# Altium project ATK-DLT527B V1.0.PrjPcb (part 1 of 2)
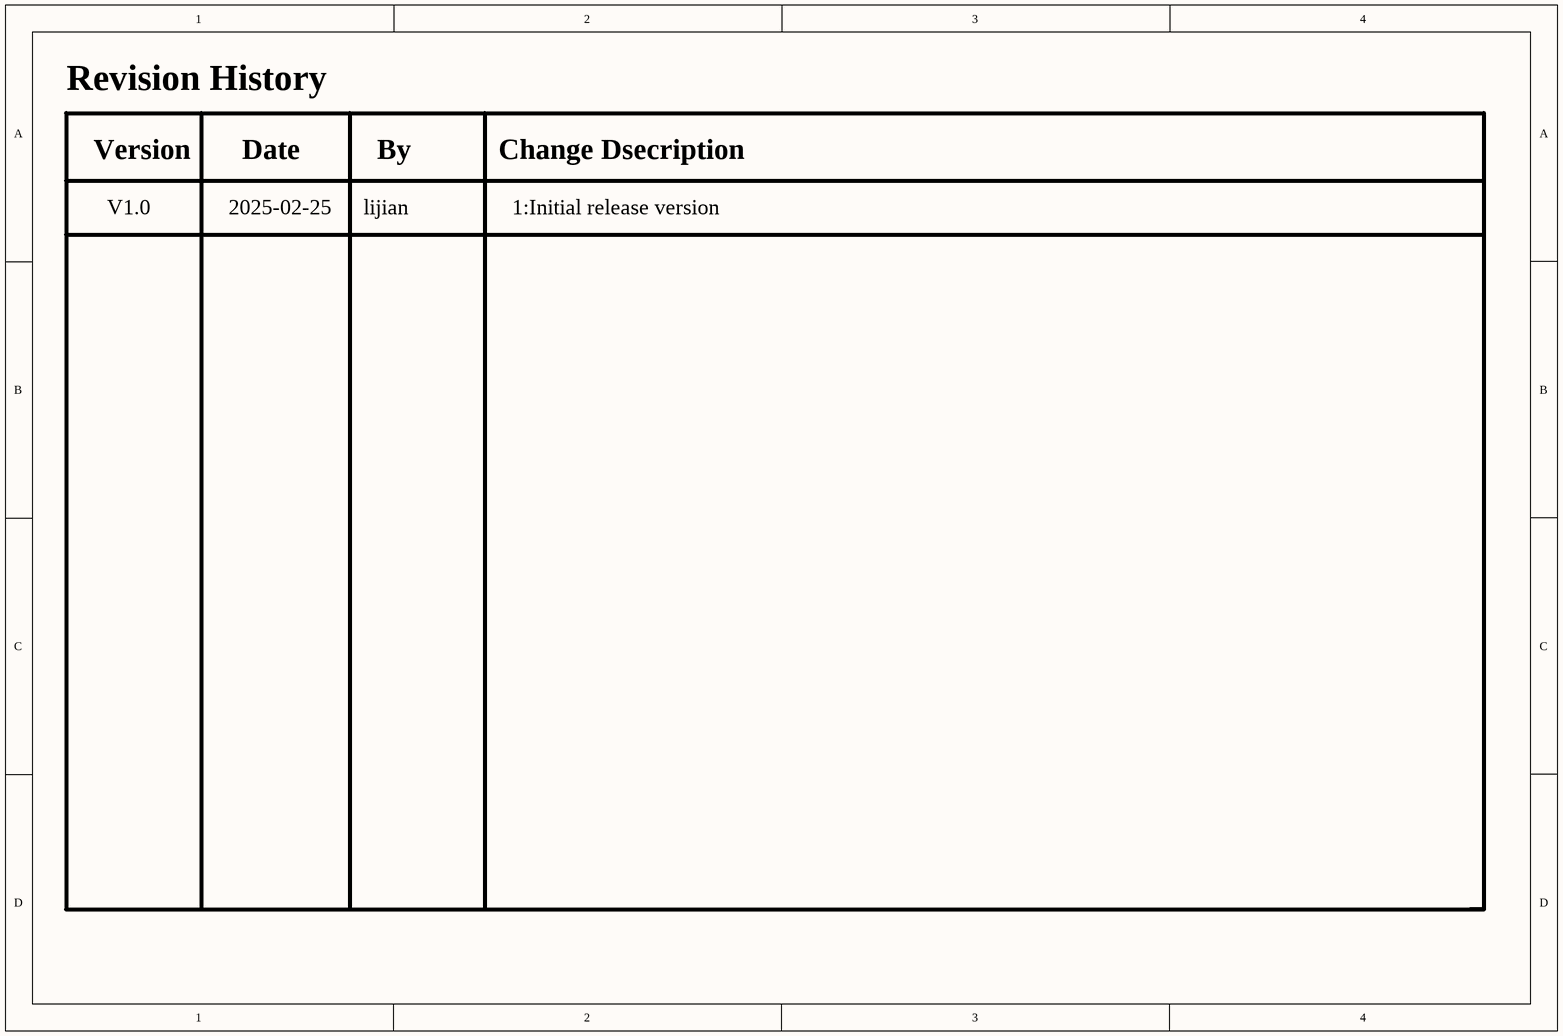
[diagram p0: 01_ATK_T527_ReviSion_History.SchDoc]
13 sheets, 679 parts. Net scope: global (net labels, ports and power ports of the same name join across sheets).
Sheets:
  01_ATK_T527_ReviSion_History.SchDoc
  02_ATK_T527_CORE.SchDoc
  03_ATK_T527_POWER.SchDoc
  04_ATK_T527_NET1.SchDoc
  05_ATK_T527_NET2.SchDoc
  06_ATK_T527_DISPLAY.SchDoc
  07_ATK_T527_HDMI&DP.SchDoc
  08_ATK_T527_USBOTG&HOST.SchDoc
  09_ATK_T527_AUDIO.SchDoc
  10_ATK_T527_MIPICSI.SchDoc
  11_ATK_T527_CAN485.SchDoc
  12_ATK_T527_DEVICE1.SchDoc
  13_ATK_T527_DEVICE2.SchDoc

## Sheet 01_ATK_T527_ReviSion_History.SchDoc
size A4; Organization: Altium Limited; Address1: L3, 12a Rodborough Rd; Address2: Frenchs Forest; Address3: NSW; Address4: Australia 2086

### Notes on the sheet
- Revision History
- Version
- Date
- By
- Change Dsecription
- V1.0
- 2025-02-25
- lijian
- 1:Initial release version

## Sheet 02_ATK_T527_CORE.SchDoc
size A3; Date: 13; Author: ALIENTEK; Revision: 0; Version: V1.0; SheetSize: A3
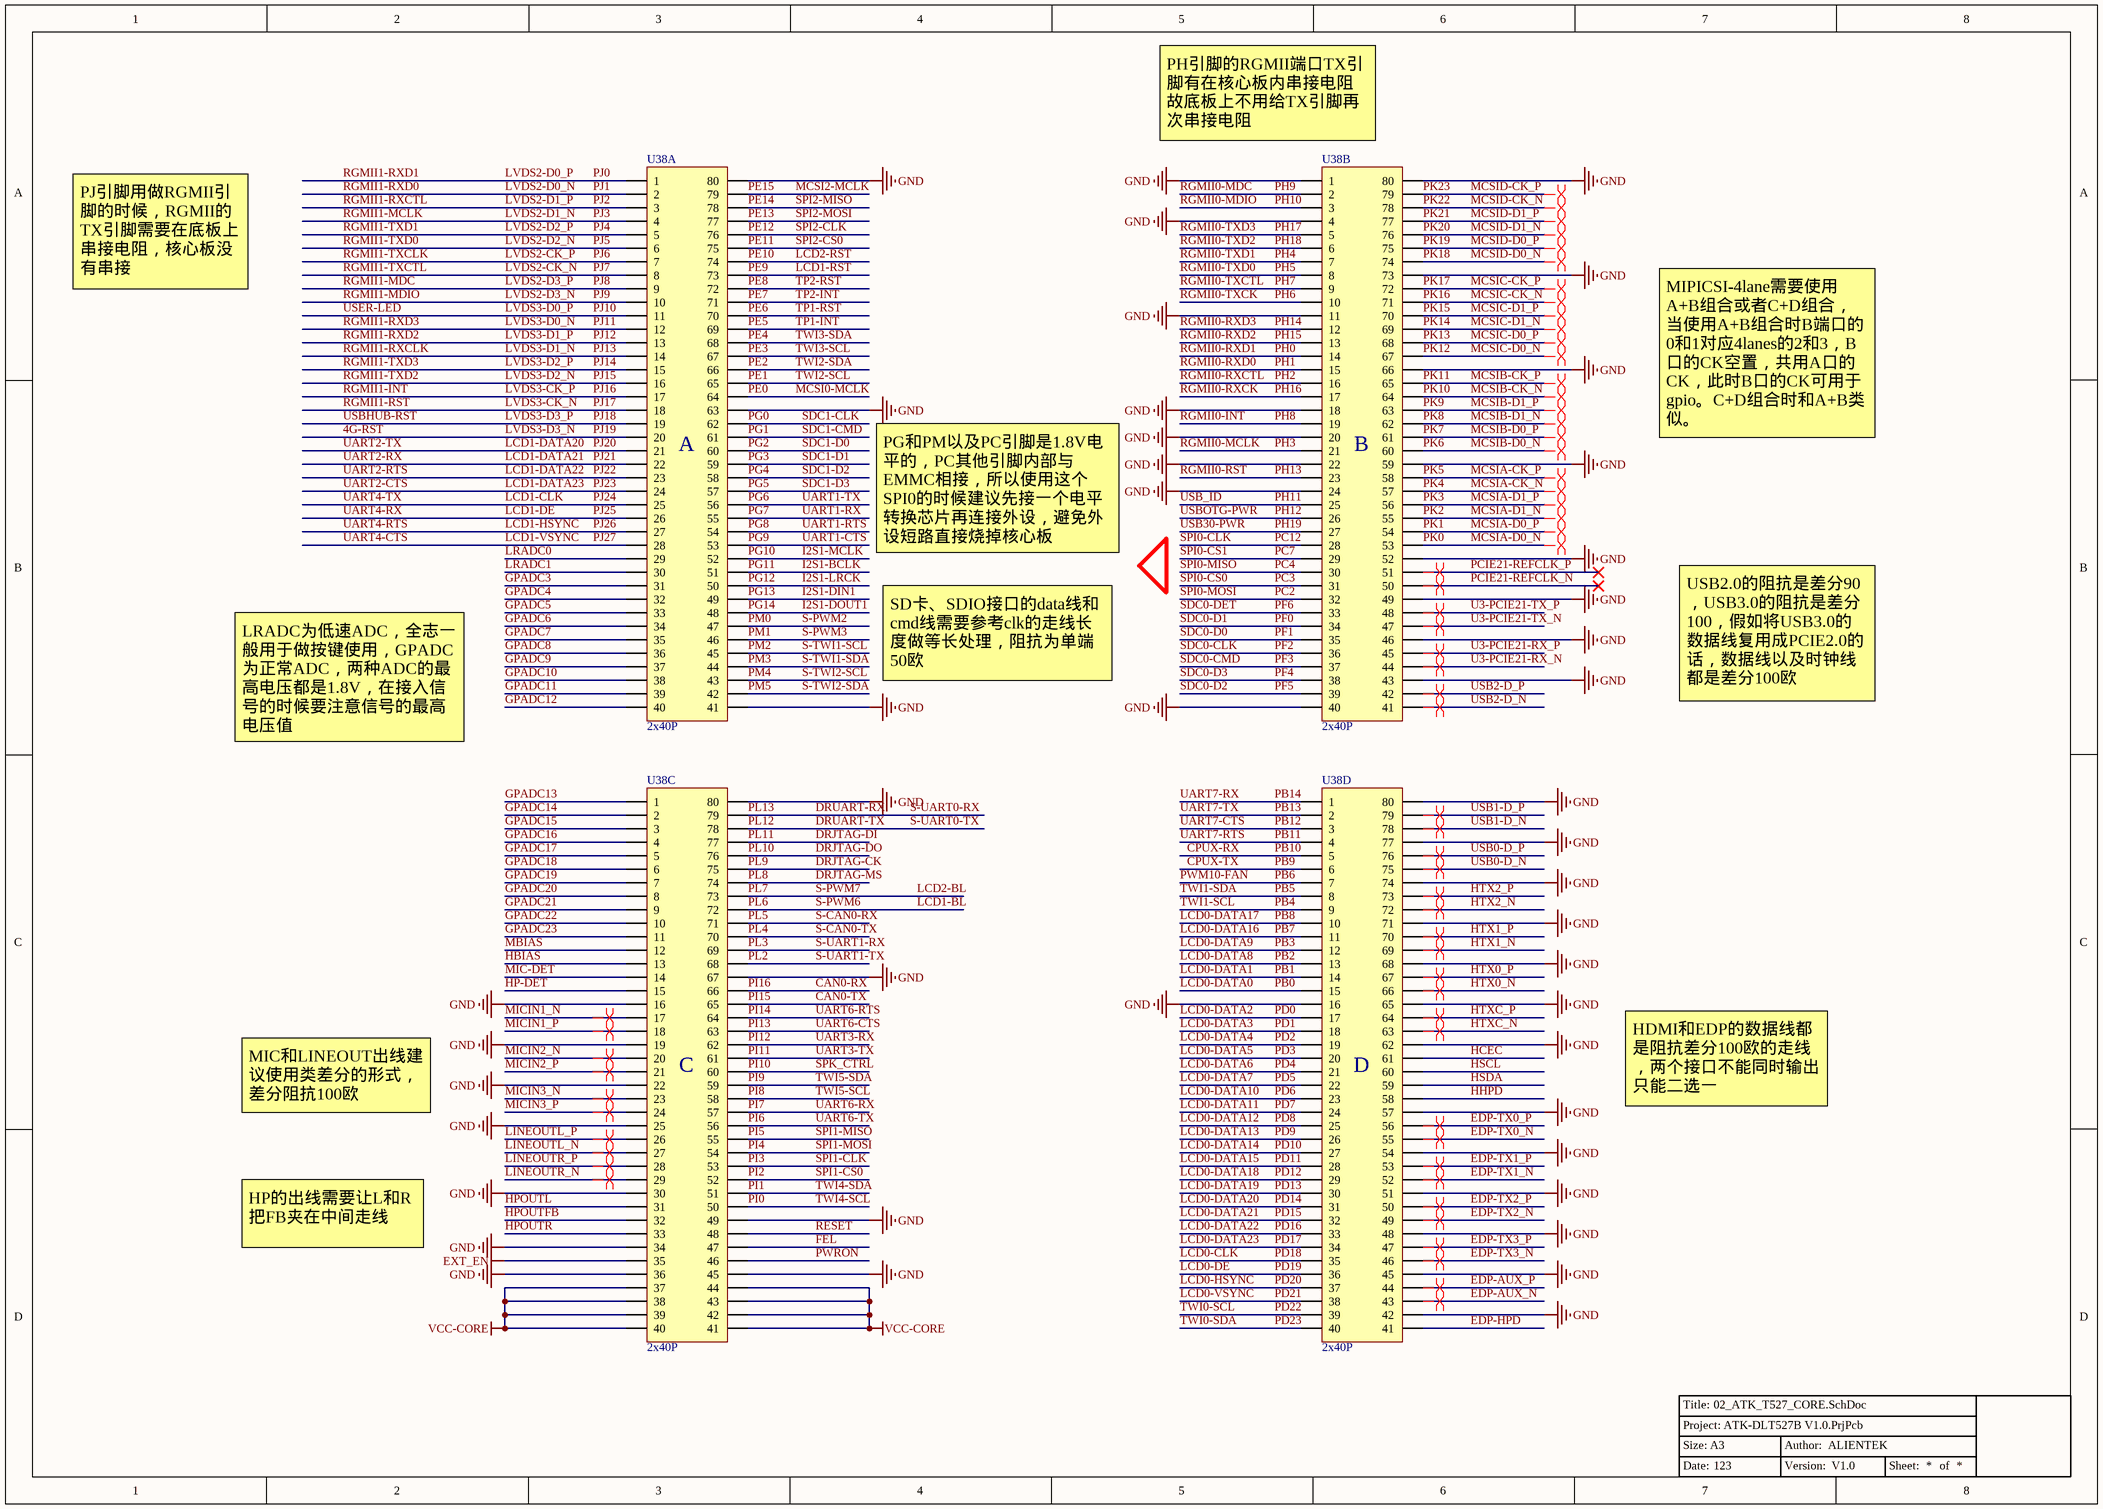
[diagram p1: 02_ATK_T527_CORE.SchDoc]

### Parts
U38  2x40P  [ATK-CLT527B-CORE]  (parts A,B,C,D of 4)

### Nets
EXT_EN: U38.C35(35)
GND: U38.A41(41) U38.A63(63) U38.A80(80) U38.B1(1) U38.B4(4) U38.B11(11) U38.B18(18) U38.B20(20) U38.B22(22) U38.B24(24) U38.B40(40) U38.B43(43) U38.B46(46) U38.B49(49) U38.B52(52) U38.B59(59) U38.B66(66) U38.B73(73) U38.B80(80) U38.C16(16) U38.C19(19) U38.C22(22) U38.C25(25) U38.C30(30) U38.C34(34) U38.C36(36) U38.C45(45) U38.C49(49) U38.C67(67) U38.C80(80) U38.D16(16) U38.D42(42) U38.D45(45) U38.D48(48) U38.D51(51) U38.D54(54) U38.D57(57) U38.D62(62) U38.D65(65) U38.D68(68) U38.D71(71) U38.D74(74) U38.D77(77) U38.D80(80)
VCC-CORE: U38.C37(37) U38.C38(38) U38.C39(39) U38.C40(40) U38.C41(41) U38.C42(42) U38.C43(43) U38.C44(44)
4G-RST: U38.A20(20)  [also labelled LVDS3-D3_N, PJ19]
CAN0-RX: U38.C66(66)  [also labelled PI16]
CAN0-TX: U38.C65(65)  [also labelled PI15]
CPUX-RX: U38.D5(5)  [also labelled PB10]
CPUX-TX: U38.D6(6)  [also labelled PB9]
DRJTAG-CK: U38.C75(75)  [also labelled PL9]
DRJTAG-DI: U38.C77(77)  [also labelled PL11]
DRJTAG-DO: U38.C76(76)  [also labelled PL10]
DRJTAG-MS: U38.C74(74)  [also labelled PL8]
DRUART-RX: U38.C79(79)  [also labelled PL13, S-UART0-RX]
DRUART-TX: U38.C78(78)  [also labelled PL12, S-UART0-TX]
EDP-AUX_N: U38.D43(43)
EDP-AUX_P: U38.D44(44)
EDP-HPD: U38.D41(41)
EDP-TX0_N: U38.D55(55)
EDP-TX0_P: U38.D56(56)
EDP-TX1_N: U38.D52(52)
EDP-TX1_P: U38.D53(53)
EDP-TX2_N: U38.D49(49)
EDP-TX2_P: U38.D50(50)
EDP-TX3_N: U38.D46(46)
EDP-TX3_P: U38.D47(47)
FEL: U38.C47(47)
GPADC3: U38.A31(31)
GPADC4: U38.A32(32)
GPADC5: U38.A33(33)
GPADC6: U38.A34(34)
GPADC7: U38.A35(35)
GPADC8: U38.A36(36)
GPADC9: U38.A37(37)
GPADC10: U38.A38(38)
GPADC11: U38.A39(39)
GPADC12: U38.A40(40)
GPADC13: U38.C1(1)
GPADC14: U38.C2(2)
GPADC15: U38.C3(3)
GPADC16: U38.C4(4)
GPADC17: U38.C5(5)
GPADC18: U38.C6(6)
GPADC19: U38.C7(7)
GPADC20: U38.C8(8)
GPADC21: U38.C9(9)
GPADC22: U38.C10(10)
GPADC23: U38.C11(11)
HBIAS: U38.C13(13)
HCEC: U38.D61(61)
HHPD: U38.D58(58)
HP-DET: U38.C15(15)
HPOUTFB: U38.C32(32)
HPOUTL: U38.C31(31)
HPOUTR: U38.C33(33)
HSCL: U38.D60(60)
HSDA: U38.D59(59)
HTX0_N: U38.D66(66)
HTX0_P: U38.D67(67)
HTX1_N: U38.D69(69)
HTX1_P: U38.D70(70)
HTX2_N: U38.D72(72)
HTX2_P: U38.D73(73)
HTXC_N: U38.D63(63)
HTXC_P: U38.D64(64)
I2S1-BCLK: U38.A51(51)  [also labelled PG11]
I2S1-DIN1: U38.A49(49)  [also labelled PG13]
I2S1-DOUT1: U38.A48(48)  [also labelled PG14]
I2S1-LRCK: U38.A50(50)  [also labelled PG12]
I2S1-MCLK: U38.A52(52)  [also labelled PG10]
LCD0-CLK: U38.D35(35)  [also labelled PD18]
LCD0-DATA0: U38.D15(15)  [also labelled PB0]
LCD0-DATA1: U38.D14(14)  [also labelled PB1]
LCD0-DATA2: U38.D17(17)  [also labelled PD0]
LCD0-DATA3: U38.D18(18)  [also labelled PD1]
LCD0-DATA4: U38.D19(19)  [also labelled PD2]
LCD0-DATA5: U38.D20(20)  [also labelled PD3]
LCD0-DATA6: U38.D21(21)  [also labelled PD4]
LCD0-DATA7: U38.D22(22)  [also labelled PD5]
LCD0-DATA8: U38.D13(13)  [also labelled PB2]
LCD0-DATA9: U38.D12(12)  [also labelled PB3]
LCD0-DATA10: U38.D23(23)  [also labelled PD6]
LCD0-DATA11: U38.D24(24)  [also labelled PD7]
LCD0-DATA12: U38.D25(25)  [also labelled PD8]
LCD0-DATA13: U38.D26(26)  [also labelled PD9]
LCD0-DATA14: U38.D27(27)  [also labelled PD10]
LCD0-DATA15: U38.D28(28)  [also labelled PD11]
LCD0-DATA16: U38.D11(11)  [also labelled PB7]
LCD0-DATA17: U38.D10(10)  [also labelled PB8]
LCD0-DATA18: U38.D29(29)  [also labelled PD12]
LCD0-DATA19: U38.D30(30)  [also labelled PD13]
LCD0-DATA20: U38.D31(31)  [also labelled PD14]
LCD0-DATA21: U38.D32(32)  [also labelled PD15]
LCD0-DATA22: U38.D33(33)  [also labelled PD16]
LCD0-DATA23: U38.D34(34)  [also labelled PD17]
LCD0-DE: U38.D36(36)  [also labelled PD19]
LCD0-HSYNC: U38.D37(37)  [also labelled PD20]
LCD0-VSYNC: U38.D38(38)  [also labelled PD21]
LCD1-BL: U38.C72(72)  [also labelled PL6, S-PWM6]
LCD1-CLK: U38.A25(25)  [also labelled PJ24, UART4-TX]
LCD1-DATA20: U38.A21(21)  [also labelled PJ20, UART2-TX]
LCD1-DATA21: U38.A22(22)  [also labelled PJ21, UART2-RX]
LCD1-DATA22: U38.A23(23)  [also labelled PJ22, UART2-RTS]
LCD1-DATA23: U38.A24(24)  [also labelled PJ23, UART2-CTS]
LCD1-DE: U38.A26(26)  [also labelled PJ25, UART4-RX]
LCD1-HSYNC: U38.A27(27)  [also labelled PJ26, UART4-RTS]
LCD1-RST: U38.A73(73)  [also labelled PE9]
LCD1-VSYNC: U38.A28(28)  [also labelled PJ27, UART4-CTS]
LCD2-BL: U38.C73(73)  [also labelled PL7, S-PWM7]
LCD2-RST: U38.A74(74)  [also labelled PE10]
LINEOUTL_N: U38.C27(27)
LINEOUTL_P: U38.C26(26)
LINEOUTR_N: U38.C29(29)
LINEOUTR_P: U38.C28(28)
LRADC0: U38.A29(29)
LRADC1: U38.A30(30)
LVDS2-CK_N: U38.A8(8)  [also labelled PJ7, RGMII1-TXCTL]
LVDS2-CK_P: U38.A7(7)  [also labelled PJ6, RGMII1-TXCLK]
LVDS2-D0_N: U38.A2(2)  [also labelled PJ1, RGMII1-RXD0]
LVDS2-D0_P: U38.A1(1)  [also labelled PJ0, RGMII1-RXD1]
LVDS2-D1_N: U38.A4(4)  [also labelled PJ3, RGMII1-MCLK]
LVDS2-D1_P: U38.A3(3)  [also labelled PJ2, RGMII1-RXCTL]
LVDS2-D2_N: U38.A6(6)  [also labelled PJ5, RGMII1-TXD0]
LVDS2-D2_P: U38.A5(5)  [also labelled PJ4, RGMII1-TXD1]
LVDS2-D3_N: U38.A10(10)  [also labelled PJ9, RGMII1-MDIO]
LVDS2-D3_P: U38.A9(9)  [also labelled PJ8, RGMII1-MDC]
LVDS3-CK_N: U38.A18(18)  [also labelled PJ17, RGMII1-RST]
LVDS3-CK_P: U38.A17(17)  [also labelled PJ16, RGMII1-INT]
LVDS3-D0_N: U38.A12(12)  [also labelled PJ11, RGMII1-RXD3]
LVDS3-D0_P: U38.A11(11)  [also labelled PJ10, USER-LED]
LVDS3-D1_N: U38.A14(14)  [also labelled PJ13, RGMII1-RXCLK]
LVDS3-D1_P: U38.A13(13)  [also labelled PJ12, RGMII1-RXD2]
LVDS3-D2_N: U38.A16(16)  [also labelled PJ15, RGMII1-TXD2]
LVDS3-D2_P: U38.A15(15)  [also labelled PJ14, RGMII1-TXD3]
LVDS3-D3_P: U38.A19(19)  [also labelled PJ18, USBHUB-RST]
MBIAS: U38.C12(12)
MCSI0-MCLK: U38.A64(64)  [also labelled PE0]
MCSI2-MCLK: U38.A79(79)  [also labelled PE15]
MCSIA-CK_N: U38.B57(57)  [also labelled PK4]
MCSIA-CK_P: U38.B58(58)  [also labelled PK5]
MCSIA-D0_N: U38.B53(53)  [also labelled PK0]
MCSIA-D0_P: U38.B54(54)  [also labelled PK1]
MCSIA-D1_N: U38.B55(55)  [also labelled PK2]
MCSIA-D1_P: U38.B56(56)  [also labelled PK3]
MCSIB-CK_N: U38.B64(64)  [also labelled PK10]
MCSIB-CK_P: U38.B65(65)  [also labelled PK11]
MCSIB-D0_N: U38.B60(60)  [also labelled PK6]
MCSIB-D0_P: U38.B61(61)  [also labelled PK7]
MCSIB-D1_N: U38.B62(62)  [also labelled PK8]
MCSIB-D1_P: U38.B63(63)  [also labelled PK9]
MCSIC-CK_N: U38.B71(71)  [also labelled PK16]
MCSIC-CK_P: U38.B72(72)  [also labelled PK17]
MCSIC-D0_N: U38.B67(67)  [also labelled PK12]
MCSIC-D0_P: U38.B68(68)  [also labelled PK13]
MCSIC-D1_N: U38.B69(69)  [also labelled PK14]
MCSIC-D1_P: U38.B70(70)  [also labelled PK15]
MCSID-CK_N: U38.B78(78)  [also labelled PK22]
MCSID-CK_P: U38.B79(79)  [also labelled PK23]
MCSID-D0_N: U38.B74(74)  [also labelled PK18]
MCSID-D0_P: U38.B75(75)  [also labelled PK19]
MCSID-D1_N: U38.B76(76)  [also labelled PK20]
MCSID-D1_P: U38.B77(77)  [also labelled PK21]
MIC-DET: U38.C14(14)
MICIN1_N: U38.C17(17)
MICIN1_P: U38.C18(18)
MICIN2_N: U38.C20(20)
MICIN2_P: U38.C21(21)
MICIN3_N: U38.C23(23)
MICIN3_P: U38.C24(24)
PB4: U38.D9(9)  [also labelled TWI1-SCL]  [project net CT2_SCL]
PB5: U38.D8(8)  [also labelled TWI1-SDA]  [project net CT2_SDA]
PB6: U38.D7(7)  [also labelled PWM10-FAN]
PB11: U38.D4(4)  [also labelled UART7-RTS]
PB12: U38.D3(3)  [also labelled UART7-CTS]
PB13: U38.D2(2)  [also labelled UART7-TX]
PB14: U38.D1(1)  [also labelled UART7-RX]
PC2: U38.B32(32)  [also labelled SPI0-MOSI]
PC3: U38.B31(31)  [also labelled SPI0-CS0]
PC4: U38.B30(30)  [also labelled SPI0-MISO]
PC7: U38.B29(29)  [also labelled SPI0-CS1]
PC12: U38.B28(28)  [also labelled SPI0-CLK]
PCIE21-REFCLK_N: U38.B50(50)
PCIE21-REFCLK_P: U38.B51(51)
PD22: U38.D39(39)  [also labelled TWI0-SCL]  [project net CT1_SCL]
PD23: U38.D40(40)  [also labelled TWI0-SDA]  [project net CT1_SDA]
PE1: U38.A65(65)  [also labelled TWI2-SCL]
PE2: U38.A66(66)  [also labelled TWI2-SDA]
PE3: U38.A67(67)  [also labelled TWI3-SCL]
PE4: U38.A68(68)  [also labelled TWI3-SDA]
PE5: U38.A69(69)  [also labelled TP1-INT]  [project net CT1_INT]
PE6: U38.A70(70)  [also labelled TP1-RST]  [project net CT1_RST]
PE7: U38.A71(71)  [also labelled TP2-INT]  [project net CT2_INT]
PE8: U38.A72(72)  [also labelled TP2-RST]  [project net CT2_RST]
PE11: U38.A75(75)  [also labelled SPI2-CS0]
PE12: U38.A76(76)  [also labelled SPI2-CLK]
PE13: U38.A77(77)  [also labelled SPI2-MOSI]
PE14: U38.A78(78)  [also labelled SPI2-MISO]
PF0: U38.B34(34)  [also labelled SDC0-D1]
PF1: U38.B35(35)  [also labelled SDC0-D0]
PF2: U38.B36(36)  [also labelled SDC0-CLK]
PF3: U38.B37(37)  [also labelled SDC0-CMD]
PF4: U38.B38(38)  [also labelled SDC0-D3]
PF5: U38.B39(39)  [also labelled SDC0-D2]
PF6: U38.B33(33)  [also labelled SDC0-DET]
PG0: U38.A62(62)  [also labelled SDC1-CLK]
PG1: U38.A61(61)  [also labelled SDC1-CMD]
PG2: U38.A60(60)  [also labelled SDC1-D0]
PG3: U38.A59(59)  [also labelled SDC1-D1]
PG4: U38.A58(58)  [also labelled SDC1-D2]
PG5: U38.A57(57)  [also labelled SDC1-D3]
PG6: U38.A56(56)  [also labelled UART1-TX]
PG7: U38.A55(55)  [also labelled UART1-RX]
PG8: U38.A54(54)  [also labelled UART1-RTS]
PG9: U38.A53(53)  [also labelled UART1-CTS]
PH0: U38.B14(14)  [also labelled RGMII0-RXD1]
PH1: U38.B15(15)  [also labelled RGMII0-RXD0]
PH2: U38.B16(16)  [also labelled RGMII0-RXCTL]
PH3: U38.B21(21)  [also labelled RGMII0-MCLK]
PH4: U38.B7(7)  [also labelled RGMII0-TXD1]
PH5: U38.B8(8)  [also labelled RGMII0-TXD0]
PH6: U38.B10(10)  [also labelled RGMII0-TXCK]
PH7: U38.B9(9)  [also labelled RGMII0-TXCTL]
PH8: U38.B19(19)  [also labelled RGMII0-INT]
PH9: U38.B2(2)  [also labelled RGMII0-MDC]
PH10: U38.B3(3)  [also labelled RGMII0-MDIO]
PH11: U38.B25(25)  [also labelled USB_ID]
PH12: U38.B26(26)  [also labelled USBOTG-PWR]
PH13: U38.B23(23)  [also labelled RGMII0-RST]
PH14: U38.B12(12)  [also labelled RGMII0-RXD3]
PH15: U38.B13(13)  [also labelled RGMII0-RXD2]
PH16: U38.B17(17)  [also labelled RGMII0-RXCK]
PH17: U38.B5(5)  [also labelled RGMII0-TXD3]
PH18: U38.B6(6)  [also labelled RGMII0-TXD2]
PH19: U38.B27(27)  [also labelled USB30-PWR]
PI0: U38.C50(50)  [also labelled TWI4-SCL]
PI1: U38.C51(51)  [also labelled TWI4-SDA]
PI2: U38.C52(52)  [also labelled SPI1-CS0]
PI3: U38.C53(53)  [also labelled SPI1-CLK]
PI4: U38.C54(54)  [also labelled SPI1-MOSI]
PI5: U38.C55(55)  [also labelled SPI1-MISO]
PI6: U38.C56(56)  [also labelled UART6-TX]
PI7: U38.C57(57)  [also labelled UART6-RX]
PI8: U38.C58(58)  [also labelled TWI5-SCL]
PI9: U38.C59(59)  [also labelled TWI5-SDA]
PI10: U38.C60(60)  [also labelled SPK_CTRL]
PI11: U38.C61(61)  [also labelled UART3-TX]
PI12: U38.C62(62)  [also labelled UART3-RX]
PI13: U38.C63(63)  [also labelled UART6-CTS]
PI14: U38.C64(64)  [also labelled UART6-RTS]
PL2: U38.C68(68)  [also labelled S-UART1-TX]
PL3: U38.C69(69)  [also labelled S-UART1-RX]
PL4: U38.C70(70)  [also labelled S-CAN0-TX]
PL5: U38.C71(71)  [also labelled S-CAN0-RX]
PM0: U38.A47(47)  [also labelled S-PWM2]
PM1: U38.A46(46)  [also labelled S-PWM3]
PM2: U38.A45(45)  [also labelled S-TWI1-SCL]
PM3: U38.A44(44)  [also labelled S-TWI1-SDA]
PM4: U38.A43(43)  [also labelled S-TWI2-SCL]
PM5: U38.A42(42)  [also labelled S-TWI2-SDA]
PWRON: U38.C46(46)
RESET: U38.C48(48)
U3-PCIE21-RX_N: U38.B44(44)
U3-PCIE21-RX_P: U38.B45(45)
U3-PCIE21-TX_N: U38.B47(47)
U3-PCIE21-TX_P: U38.B48(48)
USB0-D_N: U38.D75(75)
USB0-D_P: U38.D76(76)
USB1-D_N: U38.D78(78)
USB1-D_P: U38.D79(79)
USB2-D_N: U38.B41(41)
USB2-D_P: U38.B42(42)

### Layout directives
differential pair: EDP-AUX_N, EDP-AUX_P, EDP-TX0_N, EDP-TX0_P, EDP-TX1_N, EDP-TX1_P, EDP-TX2_N, EDP-TX2_P, EDP-TX3_N, EDP-TX3_P, HTX0_N, HTX0_P, HTX1_N, HTX1_P, HTX2_N, HTX2_P, HTXC_N, HTXC_P, LINEOUTL_N, LINEOUTL_P, LINEOUTR_N, LINEOUTR_P, MCSIA-CK_N, MCSIA-CK_P, MCSIA-D0_N, MCSIA-D0_P, MCSIA-D1_N, MCSIA-D1_P, MCSIB-CK_N, MCSIB-CK_P, MCSIB-D0_N, MCSIB-D0_P, MCSIB-D1_N, MCSIB-D1_P, MCSIC-CK_N, MCSIC-CK_P, MCSIC-D0_N, MCSIC-D0_P, MCSIC-D1_N, MCSIC-D1_P, MCSID-CK_N, MCSID-CK_P, MCSID-D0_N, MCSID-D0_P, MCSID-D1_N, MCSID-D1_P, MICIN1_N, MICIN1_P, MICIN2_N, MICIN2_P, MICIN3_N, MICIN3_P, PCIE21-REFCLK_N, PCIE21-REFCLK_P, U3-PCIE21-RX_N, U3-PCIE21-RX_P, U3-PCIE21-TX_N, U3-PCIE21-TX_P, USB0-D_N, USB0-D_P, USB1-D_N, USB1-D_P, USB2-D_N, USB2-D_P

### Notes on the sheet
- (near U38) PH引脚的RGMII端口TX引脚有在核心板内串接电阻故底板上不用给TX引脚再次串接电阻
- PJ引脚用做RGMII引脚的时候，RGMII的TX引脚需要在底板上串接电阻，核心板没有串接
- MIPICSI-4lane需要使用A+B组合或者C+D组合，当使用A+B组合时B端口的0和1对应4lanes的2和3，B口的CK空置，共用A口的CK，此时B口的CK可用于gpio。C+D组合时和A+B类似。
- PG和PM以及PC引脚是1.8V电平的，PC其他引脚内部与EMMC相接，所以使用这个SPI0的时候建议先接一个电平转换芯片再连接外设，避免外设短路直接烧掉核心板
- SD卡、SDIO接口的data线和cmd线需要参考clk的走线长度做等长处理，阻抗为单端50欧
- USB2.0的阻抗是差分90，USB3.0的阻抗是差分100，假如将USB3.0的数据线复用成PCIE2.0的话，数据线以及时钟线都是差分100欧
- LRADC为低速ADC，全志一般用于做按键使用，GPADC为正常ADC，两种ADC的最高电压都是1.8V，在接入信号的时候要注意信号的最高电压值
- MIC和LINEOUT出线建议使用类差分的形式，差分阻抗100欧
- HDMI和EDP的数据线都是阻抗差分100欧的走线，两个接口不能同时输出只能二选一
- HP的出线需要让L和R把FB夹在中间走线

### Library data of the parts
U38 = CLMP257B-CORE

## Sheet 03_ATK_T527_POWER.SchDoc
size A4; Author: ALIENTEK; Revision: 0; Version: V1.0; SheetSize: A4
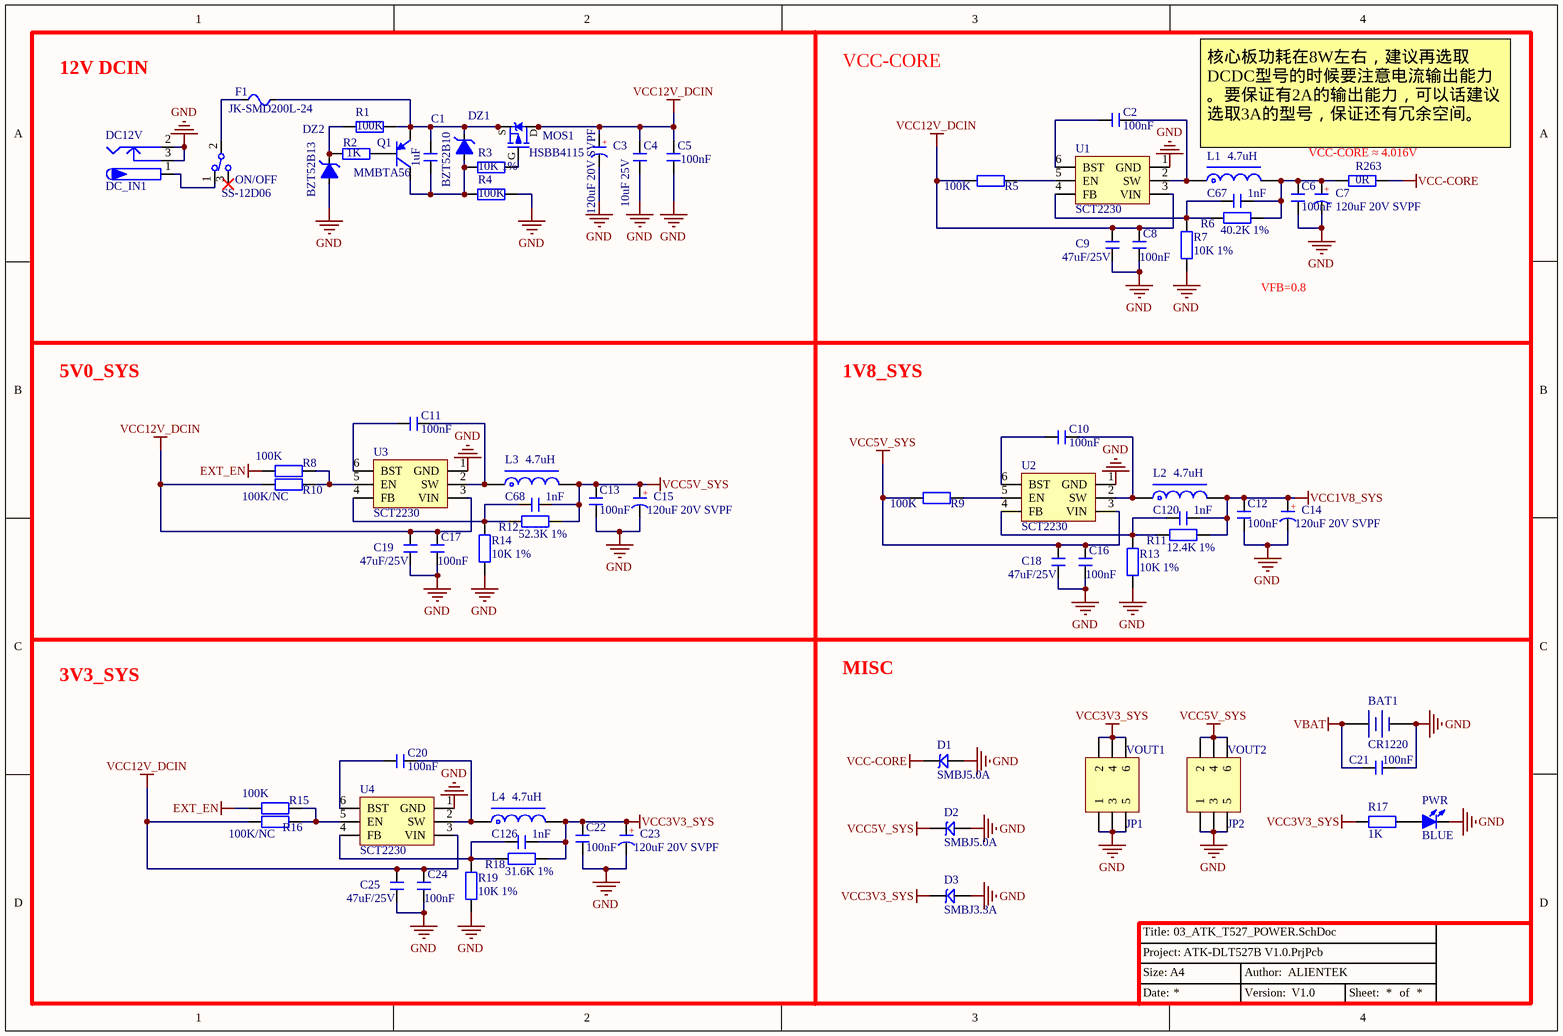
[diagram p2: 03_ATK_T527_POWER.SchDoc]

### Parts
(Parts that share a designator on the sheet are numbered #1, #2 ... from top to bottom, then left to right.)
BAT1  CR1220  [CR1220_A]
C1  1uF  [C 0402]
C2  100nF  [C 0402]
C3  120uF 20V SVPF  [CM D(6.3*7.7)]
C4  10uF 25V  [C 1206]
C5  100nF  [C 0402]
C6  100nF  [C 0402]
C7  120uF 20V SVPF  [CM D(6.3*7.7)]
C8  100nF  [C 0402]
C9  47uF/25V  [C 1206]
C10  100nF  [C 0402]
C11  100nF  [C 0402]
C12  100nF  [C 0402]
C13  100nF  [C 0402]
C14  120uF 20V SVPF  [CM D(6.3*7.7)]
C15  120uF 20V SVPF  [CM D(6.3*7.7)]
C16  100nF  [C 0402]
C17  100nF  [C 0402]
C18  47uF/25V  [C 1206]
C19  47uF/25V  [C 1206]
C20  100nF  [C 0402]
C21  100nF  [C 0402]
C22  100nF  [C 0402]
C23  120uF 20V SVPF  [CM D(6.3*7.7)]
C24  100nF  [C 0402]
C25  47uF/25V  [C 1206]
C67#1  1nF  [C 0402]
C68#1  1nF  [C 0402]
C120  1nF  [C 0402]
C126  1nF  [C 0402]
D1  SMBJ5.0A  [SMBJ]
D2  SMBJ5.0A  [SMBJ]
D3  SMBJ3.3A  [SMBJ]
DC12V  DC_IN1  [DC10B]
DZ1  BZT52B10  [SOD-123]
DZ2  BZT52B13  [SOD-123]
F1  JK-SMD200L-24  [FU 1812]
JP1  VOUT1  [Header 2.54 2X3P]
JP2  VOUT2  [Header 2.54 2X3P]
L1  4.7uH  [L-SMD-0420]
L2  4.7uH  [L-SMD-0420]
L3  4.7uH  [L-SMD-0420]
L4  4.7uH  [L-SMD-0420]
MOS1  HSBB4115  [DFN8_ 3x3]
ON/OFF  SS-12D06  [SS-12D06]
PWR  BLUE  [LED 0805B]
Q1  MMBTA56  [SOT23-3N]
R1  100K  [R 0402]
R2  1K  [R 0402]
R3  10K 1%  [R 0402]
R4  100K  [R 0402]
R5  100K  [R 0402]
R6  40.2K 1%  [R 0402]
R7  10K 1%  [R 0402]
R8  100K  [R 0402]
R9  100K  [R 0402]
R10  100K/NC  [R 0402]
R11  12.4K 1%  [R 0402]
R12  52.3K 1%  [R 0402]
R13  10K 1%  [R 0402]
R14  10K 1%  [R 0402]
R15  100K  [R 0402]
R16  100K/NC  [R 0402]
R17  1K  [R 0402]
R18  31.6K 1%  [R 0402]
R19  10K 1%  [R 0402]
R263  0R  [R 0805]
U1  SCT2230  [SOT23-6N]
U2  SCT2230  [SOT23-6N]
U3  SCT2230  [SOT23-6N]
U4  SCT2230  [SOT23-6N]

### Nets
EXT_EN: R8.1 R15.1
GND: BAT1.2(DC-) C3.2(K) C4.2 C5.2 C6.2 C7.2(K) C8.1 C9.1 C12.2 C13.2 C14.2(K) C15.2(K) C16.1 C17.1 C18.1 C19.1 C21.2 C22.2 C23.2(K) C24.1 C25.1 D1.1 D2.1 D3.1 DC12V.2 DC12V.3 DZ2.1(A) JP1.1 JP1.3 JP1.5 JP2.1 JP2.3 JP2.5 PWR.2(K) R4.2 R7.2 R13.2 R14.2 R19.2 U1.1(GND) U2.1(GND) U3.1(GND) U4.1(GND)
VBAT: BAT1.1(DC+) C21.1
VCC1V8_SYS: C12.1 C14.1(A) C120.2 L2.2 R11.2
VCC3V3_SYS: C22.1 C23.1(A) C126.2 D3.2 JP1.2 JP1.4 JP1.6 L4.2 R17.2 R18.2
VCC5V_SYS: C13.1 C15.1(A) C16.2 C18.2 C68#1.2 D2.2 JP2.2 JP2.4 JP2.6 L3.2 R9.1 R12.2 U2.3(VIN)
VCC12V_DCIN: C3.1(A) C4.1 C5.1 C8.2 C9.2 C17.2 C19.2 C24.2 C25.2 MOS1.5(D) MOS1.6(D) MOS1.7(D) MOS1.8(D) R5.1 R10.1 R16.1 U1.3(VIN) U3.3(VIN) U4.3(VIN)
VCC-CORE: D1.2 R263.2
NetC1_1: C1.1 DZ1.2(K) F1.1 MOS1.1(S) MOS1.2(S) MOS1.3(G) Q1.2(E) R1.1
NetC1_2: C1.2 DZ1.1(A) Q1.3(C) R3.1 R4.1
NetC2_1: C2.1 U1.6(BST)
NetC2_2: C2.2 L1.1 U1.2(SW)
NetC6_1: C6.1 C7.1(A) C67#1.2 L1.2 R6.2 R263.1
NetC10_1: C10.1 U2.6(BST)
NetC10_2: C10.2 L2.1 U2.2(SW)
NetC11_1: C11.1 U3.6(BST)
NetC11_2: C11.2 L3.1 U3.2(SW)
NetC20_1: C20.1 U4.6(BST)
NetC20_2: C20.2 L4.1 U4.2(SW)
NetC67#1_1: C67#1.1 R6.1 R7.1 U1.4(FB)
NetC68#1_1: C68#1.1 R12.1 R14.1 U3.4(FB)
NetC120_1: C120.1 R11.1 R13.1 U2.4(FB)
NetC126_1: C126.1 R18.1 R19.1 U4.4(FB)
NetDC12V_1: DC12V.1 ON/OFF.1
NetDZ2_2: DZ2.2(K) R1.2 R2.1
NetF1_2: F1.2 ON/OFF.2
NetMOS1_4: MOS1.4(G) R3.2
NetPWR_1: PWR.1(A) R17.1
NetQ1_1: Q1.1(B) R2.2
NetR5_2: R5.2 U1.5(EN)
NetR8_2: R8.2 R10.2 U3.5(EN)
NetR9_2: R9.2 U2.5(EN)
NetR15_2: R15.2 R16.2 U4.5(EN)

Not connected (* = marked no-connect by the designer): ON/OFF 3*

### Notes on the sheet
- 12V DCIN
- VCC-CORE
- 核心板功耗在8W左右，建议再选取DCDC型号的时候要注意电流输出能力。要保证有2A的输出能力，可以话建议选取3A的型号，保证还有冗余空间。
- VCC-CORE ≈ 4.016V
- VFB=0.8
- 5V0_SYS
- 1V8_SYS
- 3V3_SYS
- MISC

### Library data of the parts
BAT1 = CR-3V: 微型电池; 版权归属: 正点原子
C1 = C: 50V 10% 无极性贴片电容; BOM名称: 电容; 版权归属: 正点原子
C2 C4-C6 C8-C13 C16-C20 C22 C24 C25 C67#1 C68#1 C120 C126 = C: 无极性贴片电容; 版权归属: 源创客
C3 C7 C14 C15 C23 = C-CM: 贴片电解电容; 版权归属: 源创客
C21 = C: 无极性贴片电容; 版权归属: 正点原子
D1-D3 = SMBJ: TVS
DC12V = P-DC: 低压电源接口; BOM名称: DC电源接口; 版权归属: 源创客
DZ1 DZ2 = BZT52BxVx: CJ x.xV / 0.5W稳压管  2%; 版权归属: 正点原子; BOM名称: 二极管(稳压)
F1 = FU: 贴片保险丝; 版权归属: 源创客
JP1 JP2 = Header 3X2: 3*2P接插件; 版权归属: 源创客
L1-L4 = L-CDRH: 功率屏蔽电感; 版权归属: 源创客
MOS1 = HSBB6115: PMOS -60V -8A@-4.5V 33mΩ; BOM名称: MOS管; 版权归属: 正点原子
ON/OFF = SSW-1P: 1路波动开关; BOM名称: 波动开关; 版权归属: 源创客
PWR = LED-SMD: 贴片LED; 版权归属: 源创客
Q1 = 9015-SMD: 低噪放大-PNP型; BOM名称: 三极管; 版权归属: 正点原子; 属性: 50V 0.1A 0.4W 150MHZ
R1-R4 = R: 贴片电阻; BOM名称: 电阻; 版权归属: 正点原子
R5-R19 R263 = R: 贴片电阻; 版权归属: 源创客
U1-U4 = DC JW5060T_6: DC降压芯片

## Sheet 04_ATK_T527_NET1.SchDoc
size A4; Author: ALIENTEK; Revision: 0; Version: V1.0; SheetSize: A4
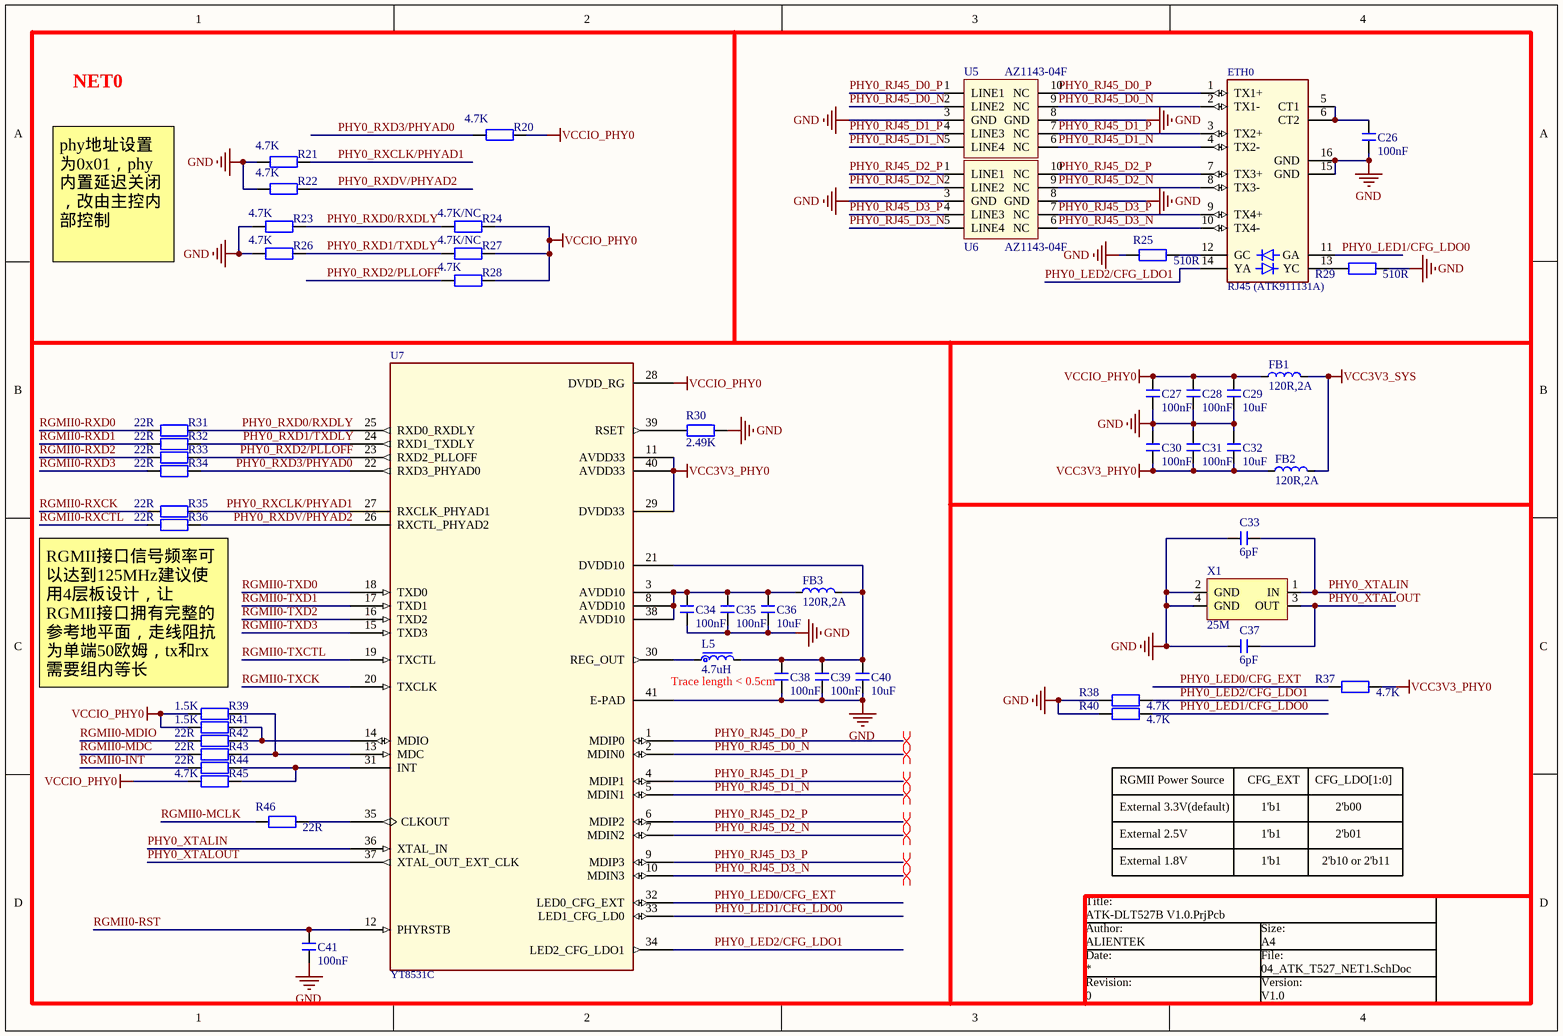
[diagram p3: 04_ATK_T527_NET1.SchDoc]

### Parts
C26  100nF  [C 0402]
C27  100nF  [C 0402]
C28  100nF  [C 0402]
C29  10uF  [C 0603]
C30  100nF  [C 0402]
C31  100nF  [C 0402]
C32  10uF  [C 0603]
C33  6pF  [C 0402]
C34  100nF  [C 0402]
C35  100nF  [C 0402]
C36  10uF  [C 0603]
C37  6pF  [C 0402]
C38  100nF  [C 0402]
C39  100nF  [C 0402]
C40  10uF  [C 0603]
C41  100nF  [C 0402]
ETH0  RJ45 (ATK911131A)  [HR911131A]
FB1  120R,2A  [L 0603]
FB2  120R,2A  [L 0603]
FB3  120R,2A  [L 0603]
L5  4.7uH  [L-2520]
R20  4.7K  [R 0402]
R21  4.7K  [R 0402]
R22  4.7K  [R 0402]
R23  4.7K  [R 0402]
R24  4.7K/NC  [R 0402]
R25  510R  [R 0402]
R26  4.7K  [R 0402]
R27  4.7K/NC  [R 0402]
R28  4.7K  [R 0402]
R29  510R  [R 0402]
R30  2.49K  [R 0402]
R31  22R  [R 0402]
R32  22R  [R 0402]
R33  22R  [R 0402]
R34  22R  [R 0402]
R35  22R  [R 0402]
R36  22R  [R 0402]
R37  4.7K  [R 0402]
R38  4.7K  [R 0402]
R39  1.5K  [R 0402]
R40  4.7K  [R 0402]
R41  1.5K  [R 0402]
R42  22R  [R 0402]
R43  22R  [R 0402]
R44  22R  [R 0402]
R45  4.7K  [R 0402]
R46  22R  [R 0402]
U5  AZ1143-04F  [DFN2510P10E]
U6  AZ1143-04F  [DFN2510P10E]
U7  YT8531C  [QFN40]
X1  25M  [XTAL-3225]

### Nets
GND: C26.2 C27.2 C28.2 C29.2 C30.1 C31.1 C32.1 C33.1 C34.2 C35.2 C36.2 C37.1 C38.2 C39.2 C40.2 C41.2 ETH0.15(GND) ETH0.16(GND) R21.1 R22.1 R23.1 R25.1 R26.1 R29.2 R30.2 R38.1 R40.1 U5.3(GND) U5.8(GND) U6.3(GND) U6.8(GND) U7.41(E-PAD) X1.2(GND) X1.4(GND)
VCC3V3_PHY0: C30.2 C31.2 C32.2 FB2.1 R37.2 U7.11(AVDD33) U7.29(DVDD33) U7.40(AVDD33)
VCC3V3_SYS: FB1.2 FB2.2
VCCIO_PHY0: C27.1 C28.1 C29.1 FB1.1 R20.2 R24.2 R27.2 R28.2 R39.1 R41.1 R45.1 U7.28(DVDD_RG)
PHY0_LED0/CFG_EXT: R37.1 U7.32(LED0_CFG_EXT)
PHY0_LED1/CFG_LDO0: ETH0.11(GA) R40.2 U7.33(LED1_CFG_LD0)
PHY0_LED2/CFG_LDO1: ETH0.14(YA) R38.2 U7.34(LED2_CFG_LDO1)
PHY0_RJ45_D0_N: ETH0.2(TX1-) U5.2(LINE2) U5.9(NC) U7.2(MDIN0)
PHY0_RJ45_D0_P: ETH0.1(TX1+) U5.1(LINE1) U5.10(NC) U7.1(MDIP0)
PHY0_RJ45_D1_N: ETH0.4(TX2-) U5.5(LINE4) U5.6(NC) U7.5(MDIN1)
PHY0_RJ45_D1_P: ETH0.3(TX2+) U5.4(LINE3) U5.7(NC) U7.4(MDIP1)
PHY0_RJ45_D2_N: ETH0.8(TX3-) U6.2(LINE2) U6.9(NC) U7.7(MDIN2)
PHY0_RJ45_D2_P: ETH0.7(TX3+) U6.1(LINE1) U6.10(NC) U7.6(MDIP2)
PHY0_RJ45_D3_N: ETH0.10(TX4-) U6.5(LINE4) U6.6(NC) U7.10(MDIN3)
PHY0_RJ45_D3_P: ETH0.9(TX4+) U6.4(LINE3) U6.7(NC) U7.9(MDIP3)
PHY0_RXCLK/PHYAD1: R21.2 R35.2 U7.27(RXCLK_PHYAD1)
PHY0_RXD0/RXDLY: R23.2 R24.1 R31.2 U7.25(RXD0_RXDLY)
PHY0_RXD1/TXDLY: R26.2 R27.1 R32.2 U7.24(RXD1_TXDLY)
PHY0_RXD2/PLLOFF: R28.1 R33.2 U7.23(RXD2_PLLOFF)
PHY0_RXD3/PHYAD0: R20.1 R34.2 U7.22(RXD3_PHYAD0)
PHY0_RXDV/PHYAD2: R22.2 R36.2 U7.26(RXCTL_PHYAD2)
PHY0_XTALIN: C33.2 U7.36(XTAL_IN) X1.1(IN)
PHY0_XTALOUT: C37.2 U7.37(XTAL_OUT_EXT_CLK) X1.3(OUT)
RGMII0-INT: R44.1  [project net PH8]
RGMII0-MCLK: R46.1  [project net PH3]
RGMII0-MDC: R43.1  [project net PH9]
RGMII0-MDIO: R42.1  [project net PH10]
RGMII0-RST: C41.1 U7.12(PHYRSTB)  [project net PH13]
RGMII0-RXCK: R35.1  [project net PH16]
RGMII0-RXCTL: R36.1  [project net PH2]
RGMII0-RXD0: R31.1  [project net PH1]
RGMII0-RXD1: R32.1  [project net PH0]
RGMII0-RXD2: R33.1  [project net PH15]
RGMII0-RXD3: R34.1  [project net PH14]
RGMII0-TXCK: U7.20(TXCLK)  [project net PH6]
RGMII0-TXCTL: U7.19(TXCTL)  [project net PH7]
RGMII0-TXD0: U7.18(TXD0)  [project net PH5]
RGMII0-TXD1: U7.17(TXD1)  [project net PH4]
RGMII0-TXD2: U7.16(TXD2)  [project net PH18]
RGMII0-TXD3: U7.15(TXD3)  [project net PH17]
NetC26_1: C26.1 ETH0.5(CT1) ETH0.6(CT2)
NetC34_1: C34.1 C35.1 C36.1 FB3.1 U7.3(AVDD10) U7.8(AVDD10) U7.38(AVDD10)
NetC38_1: C38.1 C39.1 C40.1 FB3.2 L5.2 U7.21(DVDD10)
NetETH0_12: ETH0.12(GC) R25.2
NetETH0_13: ETH0.13(YC) R29.1
NetL5_1: L5.1 U7.30(REG_OUT)
NetR30_1: R30.1 U7.39(RSET)
NetR39_2: R39.2 R43.2 U7.13(MDC)
NetR41_2: R41.2 R42.2 U7.14(MDIO)
NetR44_2: R44.2 R45.2 U7.31(INT)
NetR46_2: R46.2 U7.35(CLKOUT)

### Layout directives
differential pair: PHY0_RJ45_D0_N, PHY0_RJ45_D0_P, PHY0_RJ45_D1_N, PHY0_RJ45_D1_P, PHY0_RJ45_D2_N, PHY0_RJ45_D2_P, PHY0_RJ45_D3_N, PHY0_RJ45_D3_P

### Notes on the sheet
- NET0
- phy地址设置为0x01，phy内置延迟关闭，改由主控内部控制
- (near R36) RGMII接口信号频率可以达到125MHz建议使用4层板设计，让RGMII接口拥有完整的参考地平面，走线阻抗为单端50欧姆，tx和rx需要组内等长
- (near C38) Trace length < 0.5cm
- RGMII Power Source
- CFG_EXT
- CFG_LDO[1:0]
- External 3.3V(default)
- External 2.5V
- 1'b1
- 2'b00
- 2'b01
- External 1.8V
- 2'b10 or 2'b11

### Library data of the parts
C26-C41 = C: 无极性电容; BOM名称: 无极性贴片电容; 版权归属: 正点原子
ETH0 = HR911131A/C: 千兆以太网接口
FB1-FB3 = FB: 贴片磁珠; BOM名称: 小功率贴片电感; 版权归属: 正点原子; Parameter: 电感/磁珠
L5 = L: 电感; BOM名称: 功率屏蔽电感; 版权归属: 正点原子; Parameter: 电感/磁珠
R20-R46 = R: 电阻; BOM名称: 贴片电阻; 版权归属: 正点原子
U5 U6 = AZ1143-04F: ESD保护二极管阵列
U7 = RTL8211F-CG
X1 = XTAL-4P: 4脚无源晶振; BOM名称: 4脚晶振; 版权归属: 正点原子; Parameter: 晶振

## Sheet 05_ATK_T527_NET2.SchDoc
size A4; Author: ALIENTEK; Revision: 0; Version: V1.0; SheetSize: A4
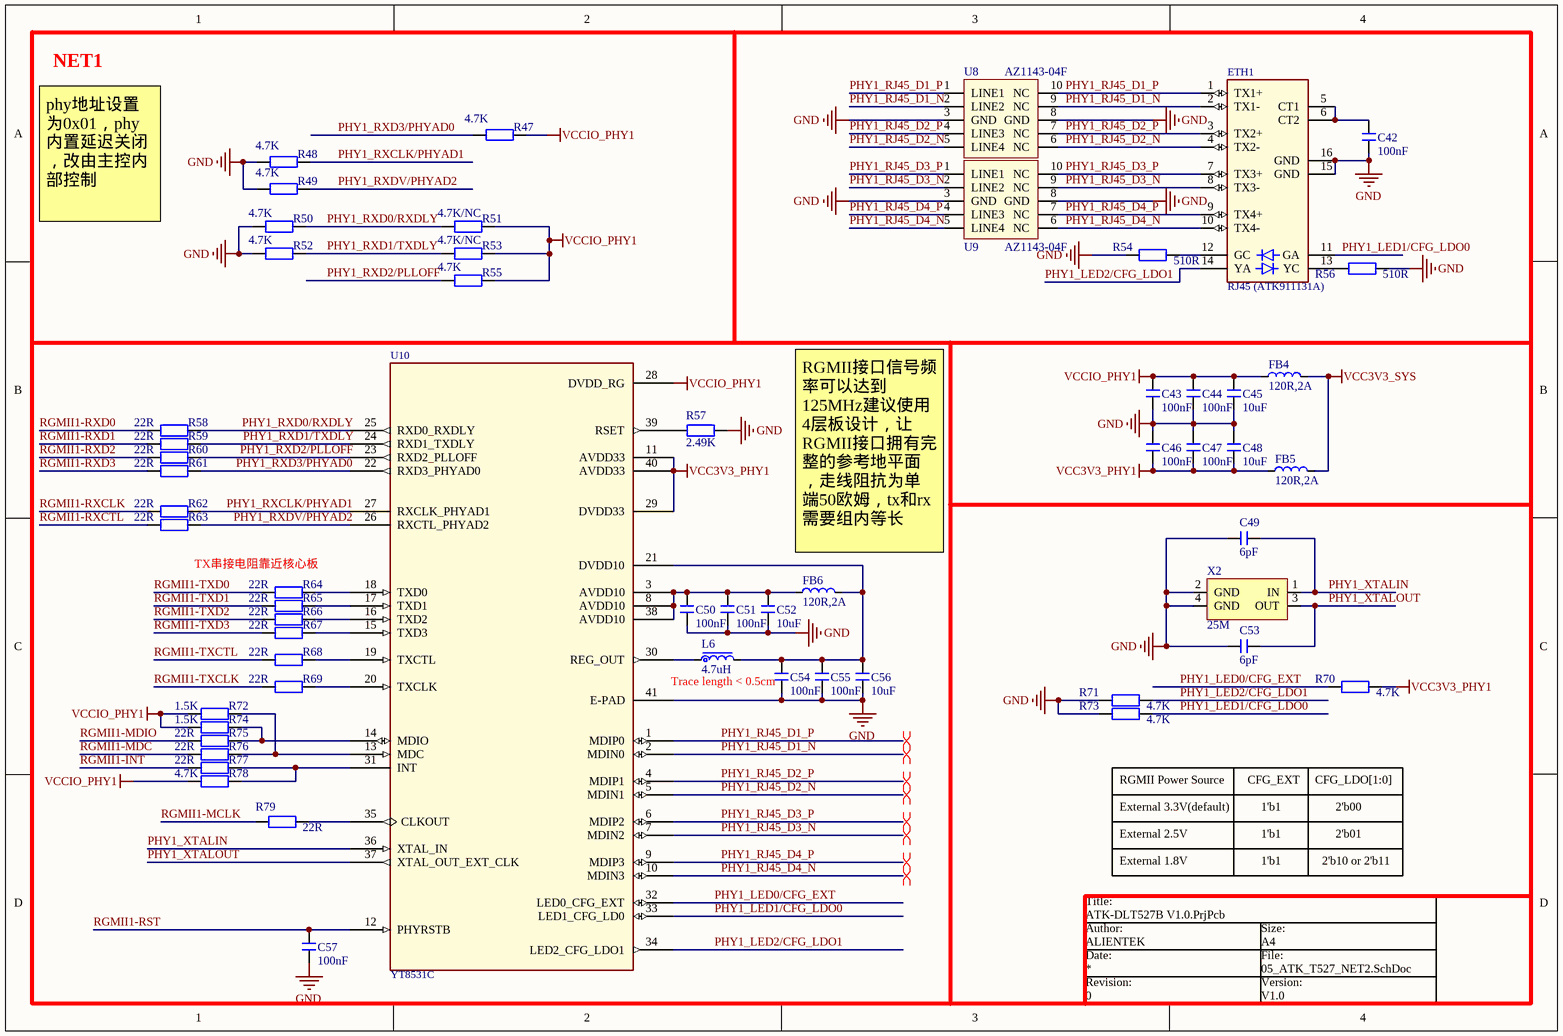
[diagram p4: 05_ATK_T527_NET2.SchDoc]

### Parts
C42  100nF  [C 0402]
C43  100nF  [C 0402]
C44  100nF  [C 0402]
C45  10uF  [C 0603]
C46  100nF  [C 0402]
C47  100nF  [C 0402]
C48  10uF  [C 0603]
C49  6pF  [C 0402]
C50  100nF  [C 0402]
C51  100nF  [C 0402]
C52  10uF  [C 0603]
C53  6pF  [C 0402]
C54  100nF  [C 0402]
C55  100nF  [C 0402]
C56  10uF  [C 0603]
C57  100nF  [C 0402]
ETH1  RJ45 (ATK911131A)  [HR911131A]
FB4  120R,2A  [L 0603]
FB5  120R,2A  [L 0603]
FB6  120R,2A  [L 0603]
L6  4.7uH  [L-2520]
R47  4.7K  [R 0402]
R48  4.7K  [R 0402]
R49  4.7K  [R 0402]
R50  4.7K  [R 0402]
R51  4.7K/NC  [R 0402]
R52  4.7K  [R 0402]
R53  4.7K/NC  [R 0402]
R54  510R  [R 0402]
R55  4.7K  [R 0402]
R56  510R  [R 0402]
R57  2.49K  [R 0402]
R58  22R  [R 0402]
R59  22R  [R 0402]
R60  22R  [R 0402]
R61  22R  [R 0402]
R62  22R  [R 0402]
R63  22R  [R 0402]
R64  22R  [R 0402]
R65  22R  [R 0402]
R66  22R  [R 0402]
R67  22R  [R 0402]
R68  22R  [R 0402]
R69  22R  [R 0402]
R70  4.7K  [R 0402]
R71  4.7K  [R 0402]
R72  1.5K  [R 0402]
R73  4.7K  [R 0402]
R74  1.5K  [R 0402]
R75  22R  [R 0402]
R76  22R  [R 0402]
R77  22R  [R 0402]
R78  4.7K  [R 0402]
R79  22R  [R 0402]
U8  AZ1143-04F  [DFN2510P10E]
U9  AZ1143-04F  [DFN2510P10E]
U10  YT8531C  [QFN40]
X2  25M  [XTAL-3225]

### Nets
GND: C42.2 C43.2 C44.2 C45.2 C46.1 C47.1 C48.1 C49.1 C50.2 C51.2 C52.2 C53.1 C54.2 C55.2 C56.2 C57.2 ETH1.15(GND) ETH1.16(GND) R48.1 R49.1 R50.1 R52.1 R54.1 R56.2 R57.2 R71.1 R73.1 U8.3(GND) U8.8(GND) U9.3(GND) U9.8(GND) U10.41(E-PAD) X2.2(GND) X2.4(GND)
VCC3V3_PHY1: C46.2 C47.2 C48.2 FB5.1 R70.2 U10.11(AVDD33) U10.29(DVDD33) U10.40(AVDD33)
VCC3V3_SYS: FB4.2 FB5.2
VCCIO_PHY1: C43.1 C44.1 C45.1 FB4.1 R47.2 R51.2 R53.2 R55.2 R72.1 R74.1 R78.1 U10.28(DVDD_RG)
PHY1_LED0/CFG_EXT: R70.1 U10.32(LED0_CFG_EXT)
PHY1_LED1/CFG_LDO0: ETH1.11(GA) R73.2 U10.33(LED1_CFG_LD0)
PHY1_LED2/CFG_LDO1: ETH1.14(YA) R71.2 U10.34(LED2_CFG_LDO1)
PHY1_RJ45_D1_N: ETH1.2(TX1-) U8.2(LINE2) U8.9(NC) U10.2(MDIN0)
PHY1_RJ45_D1_P: ETH1.1(TX1+) U8.1(LINE1) U8.10(NC) U10.1(MDIP0)
PHY1_RJ45_D2_N: ETH1.4(TX2-) U8.5(LINE4) U8.6(NC) U10.5(MDIN1)
PHY1_RJ45_D2_P: ETH1.3(TX2+) U8.4(LINE3) U8.7(NC) U10.4(MDIP1)
PHY1_RJ45_D3_N: ETH1.8(TX3-) U9.2(LINE2) U9.9(NC) U10.7(MDIN2)
PHY1_RJ45_D3_P: ETH1.7(TX3+) U9.1(LINE1) U9.10(NC) U10.6(MDIP2)
PHY1_RJ45_D4_N: ETH1.10(TX4-) U9.5(LINE4) U9.6(NC) U10.10(MDIN3)
PHY1_RJ45_D4_P: ETH1.9(TX4+) U9.4(LINE3) U9.7(NC) U10.9(MDIP3)
PHY1_RXCLK/PHYAD1: R48.2 R62.2 U10.27(RXCLK_PHYAD1)
PHY1_RXD0/RXDLY: R50.2 R51.1 R58.2 U10.25(RXD0_RXDLY)
PHY1_RXD1/TXDLY: R52.2 R53.1 R59.2 U10.24(RXD1_TXDLY)
PHY1_RXD2/PLLOFF: R55.1 R60.2 U10.23(RXD2_PLLOFF)
PHY1_RXD3/PHYAD0: R47.1 R61.2 U10.22(RXD3_PHYAD0)
PHY1_RXDV/PHYAD2: R49.2 R63.2 U10.26(RXCTL_PHYAD2)
PHY1_XTALIN: C49.2 U10.36(XTAL_IN) X2.1(IN)
PHY1_XTALOUT: C53.2 U10.37(XTAL_OUT_EXT_CLK) X2.3(OUT)
RGMII1-INT: R77.1  [project net LVDS3-CK_P]
RGMII1-MCLK: R79.1  [project net LVDS2-D1_N]
RGMII1-MDC: R76.1  [project net LVDS2-D3_P]
RGMII1-MDIO: R75.1  [project net LVDS2-D3_N]
RGMII1-RST: C57.1 U10.12(PHYRSTB)  [project net LVDS3-CK_N]
RGMII1-RXCLK: R62.1  [project net LVDS3-D1_N]
RGMII1-RXCTL: R63.1  [project net LVDS2-D1_P]
RGMII1-RXD0: R58.1  [project net LVDS2-D0_N]
RGMII1-RXD1: R59.1  [project net LVDS2-D0_P]
RGMII1-RXD2: R60.1  [project net LVDS3-D1_P]
RGMII1-RXD3: R61.1  [project net LVDS3-D0_N]
RGMII1-TXCLK: R69.1  [project net LVDS2-CK_P]
RGMII1-TXCTL: R68.1  [project net LVDS2-CK_N]
RGMII1-TXD0: R64.1  [project net LVDS2-D2_N]
RGMII1-TXD1: R65.1  [project net LVDS2-D2_P]
RGMII1-TXD2: R66.1  [project net LVDS3-D2_N]
RGMII1-TXD3: R67.1  [project net LVDS3-D2_P]
NetC42_1: C42.1 ETH1.5(CT1) ETH1.6(CT2)
NetC50_1: C50.1 C51.1 C52.1 FB6.1 U10.3(AVDD10) U10.8(AVDD10) U10.38(AVDD10)
NetC54_1: C54.1 C55.1 C56.1 FB6.2 L6.2 U10.21(DVDD10)
NetETH1_12: ETH1.12(GC) R54.2
NetETH1_13: ETH1.13(YC) R56.1
NetL6_1: L6.1 U10.30(REG_OUT)
NetR57_1: R57.1 U10.39(RSET)
NetR64_2: R64.2 U10.18(TXD0)
NetR65_2: R65.2 U10.17(TXD1)
NetR66_2: R66.2 U10.16(TXD2)
NetR67_2: R67.2 U10.15(TXD3)
NetR68_2: R68.2 U10.19(TXCTL)
NetR69_2: R69.2 U10.20(TXCLK)
NetR72_2: R72.2 R76.2 U10.13(MDC)
NetR74_2: R74.2 R75.2 U10.14(MDIO)
NetR77_2: R77.2 R78.2 U10.31(INT)
NetR79_2: R79.2 U10.35(CLKOUT)

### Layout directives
differential pair: PHY1_RJ45_D1_N, PHY1_RJ45_D1_P, PHY1_RJ45_D2_N, PHY1_RJ45_D2_P, PHY1_RJ45_D3_N, PHY1_RJ45_D3_P, PHY1_RJ45_D4_N, PHY1_RJ45_D4_P

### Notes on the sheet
- NET1
- phy地址设置为0x01，phy内置延迟关闭，改由主控内部控制
- TX串接电阻靠近核心板
- RGMII接口信号频率可以达到125MHz建议使用4层板设计，让RGMII接口拥有完整的参考地平面，走线阻抗为单端50欧姆，tx和rx需要组内等长
- (near C54) Trace length < 0.5cm
- RGMII Power Source
- CFG_EXT
- CFG_LDO[1:0]
- External 3.3V(default)
- External 2.5V
- 1'b1
- 2'b00
- 2'b01
- External 1.8V
- 2'b10 or 2'b11

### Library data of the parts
C42-C57 = C: 无极性电容; BOM名称: 无极性贴片电容; 版权归属: 正点原子
ETH1 = HR911131A/C: 千兆以太网接口
FB4-FB6 = FB: as FB1 on sheet 04_ATK_T527_NET1
L6 = L: as L5 on sheet 04_ATK_T527_NET1
R47-R79 = R: 电阻; BOM名称: 贴片电阻; 版权归属: 正点原子
U8 U9 = AZ1143-04F: ESD保护二极管阵列
U10 = RTL8211F-CG
X2 = XTAL-4P: as X1 on sheet 04_ATK_T527_NET1

## Sheet 06_ATK_T527_DISPLAY.SchDoc
size A3; Date: 13; Author: ALIENTEK; Revision: 0; Version: V1.0; SheetSize: A3
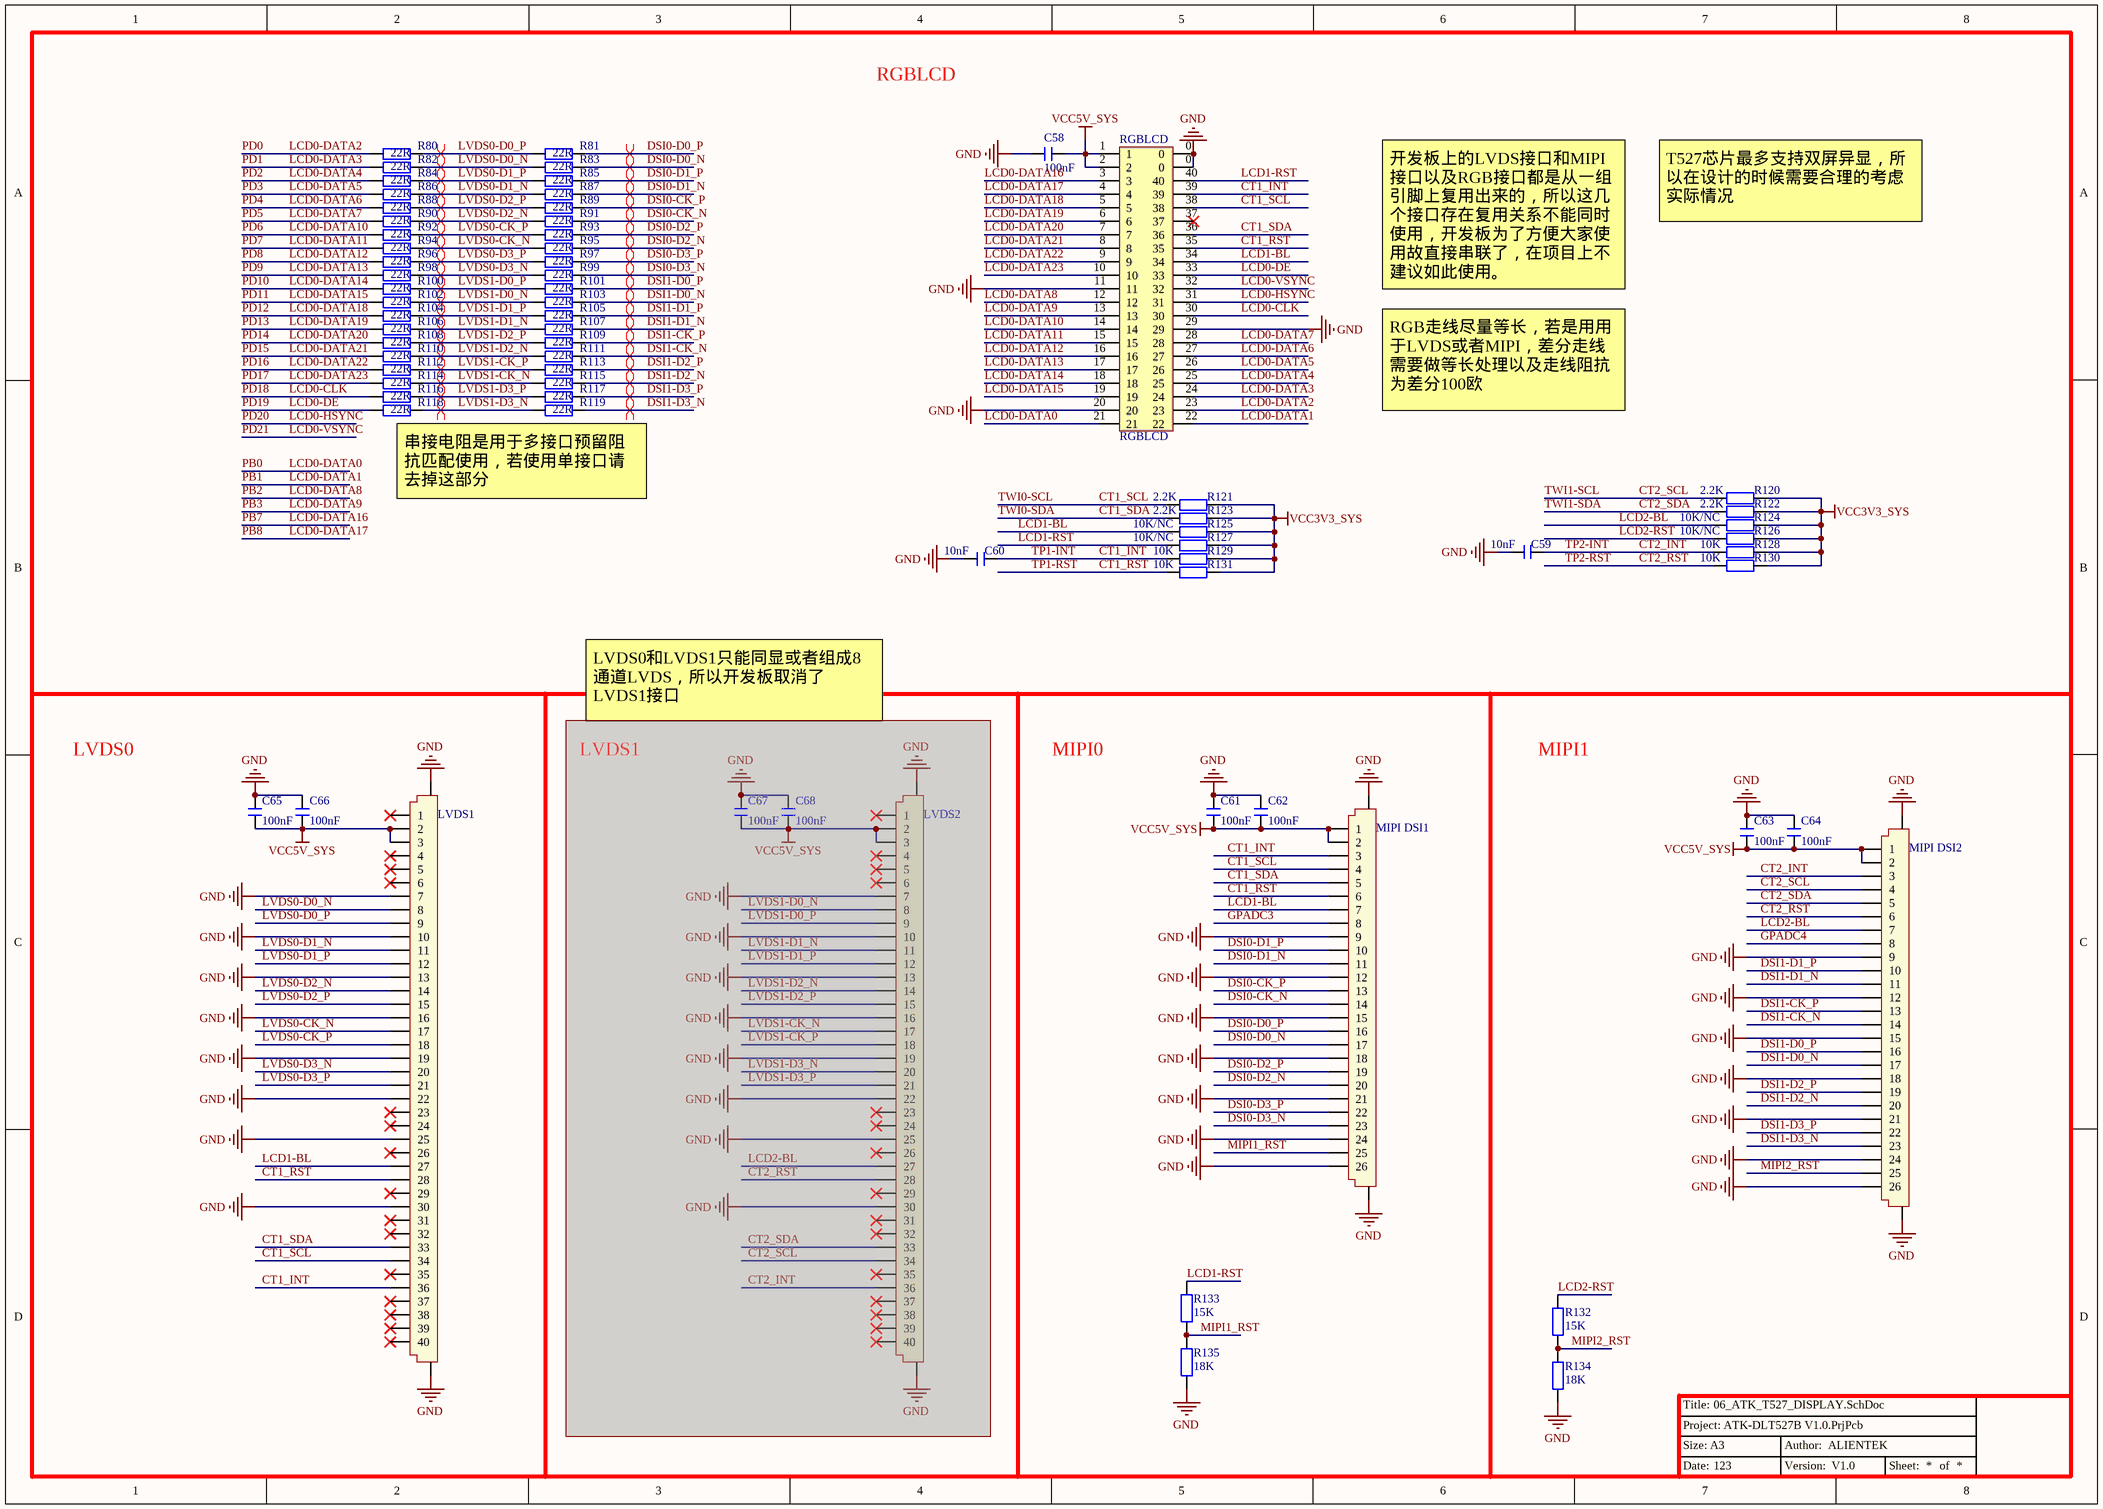
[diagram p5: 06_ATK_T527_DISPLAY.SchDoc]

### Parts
(Parts that share a designator on the sheet are numbered #1, #2 ... from top to bottom, then left to right.)
C58  100nF  [C 0402]
C59  10nF  [C 0402]
C60  10nF  [C 0402]
C61  100nF  [C 0402]
C62  100nF  [C 0402]
C63  100nF  [C 0402]
C64  100nF  [C 0402]
C65  100nF  [C 0402]
C66  100nF  [C 0402]
C67#2  100nF  [C 0402]  (masked out: inside a compile mask, not in the netlist)
C68#2  100nF  [C 0402]  (masked out: inside a compile mask, not in the netlist)
LVDS1  FPC0.5-40P  [FPC 0.5 40P V-S]  (value not drawn)
LVDS2  FPC0.5-40P  [FPC 0.5 40P V-S]  (value not drawn)  (masked out: inside a compile mask, not in the netlist)
MIPI_DSI1  FPC0.5-26P  [FPC 0.5 26P V-S]  (value not drawn)
MIPI_DSI2  FPC0.5-26P  [FPC 0.5 26P V-S]  (value not drawn)
R80  22R  [R 0402]
R81  22R  [R 0402]
R82  22R  [R 0402]
R83  22R  [R 0402]
R84  22R  [R 0402]
R85  22R  [R 0402]
R86  22R  [R 0402]
R87  22R  [R 0402]
R88  22R  [R 0402]
R89  22R  [R 0402]
R90  22R  [R 0402]
R91  22R  [R 0402]
R92  22R  [R 0402]
R93  22R  [R 0402]
R94  22R  [R 0402]
R95  22R  [R 0402]
R96  22R  [R 0402]
R97  22R  [R 0402]
R98  22R  [R 0402]
R99  22R  [R 0402]
R100  22R  [R 0402]
R101  22R  [R 0402]
R102  22R  [R 0402]
R103  22R  [R 0402]
R104  22R  [R 0402]
R105  22R  [R 0402]
R106  22R  [R 0402]
R107  22R  [R 0402]
R108  22R  [R 0402]
R109  22R  [R 0402]
R110  22R  [R 0402]
R111  22R  [R 0402]
R112  22R  [R 0402]
R113  22R  [R 0402]
R114  22R  [R 0402]
R115  22R  [R 0402]
R116  22R  [R 0402]
R117  22R  [R 0402]
R118  22R  [R 0402]
R119  22R  [R 0402]
R120  2.2K  [R 0402]
R121  2.2K  [R 0402]
R122  2.2K  [R 0402]
R123  2.2K  [R 0402]
R124  10K/NC  [R 0402]
R125  10K/NC  [R 0402]
R126  10K/NC  [R 0402]
R127  10K/NC  [R 0402]
R128  10K  [R 0402]
R129  10K  [R 0402]
R130  10K  [R 0402]
R131  10K  [R 0402]
R132  15K  [R 0402]
R133  15K  [R 0402]
R134  18K  [R 0402]
R135  18K  [R 0402]
RGBLCD  RGBLCD  [FPC 0.5 40P V-S]

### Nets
GND: C58.2 C59.2 C60.2 C61.1 C62.1 C63.1 C64.1 C65.1 C66.1 LVDS1.0 LVDS1.7 LVDS1.10 LVDS1.13 LVDS1.16 LVDS1.19 LVDS1.22 LVDS1.25 LVDS1.30 MIPI_DSI1.0 MIPI_DSI1.9 MIPI_DSI1.12 MIPI_DSI1.15 MIPI_DSI1.18 MIPI_DSI1.21 MIPI_DSI1.24 MIPI_DSI1.26 MIPI_DSI2.0 MIPI_DSI2.9 MIPI_DSI2.12 MIPI_DSI2.15 MIPI_DSI2.18 MIPI_DSI2.21 MIPI_DSI2.24 MIPI_DSI2.26 R134.1 R135.1 RGBLCD.0 RGBLCD.11 RGBLCD.20 RGBLCD.29
VCC3V3_SYS: R120.1 R121.1 R122.1 R123.1 R124.1 R125.1 R126.1 R127.1 R128.1 R129.1 R130.1 R131.1
VCC5V_SYS: C58.1 C61.2 C62.2 C63.2 C64.2 C65.2 C66.2 LVDS1.2 LVDS1.3 MIPI_DSI1.1 MIPI_DSI1.2 MIPI_DSI2.1 MIPI_DSI2.2 RGBLCD.1 RGBLCD.2
CT1_INT: C60.1 LVDS1.36 MIPI_DSI1.3 R129.2 RGBLCD.39  [also labelled TP1-INT]
CT1_RST: LVDS1.28 MIPI_DSI1.6 R131.2 RGBLCD.35  [also labelled TP1-RST]
CT1_SCL: LVDS1.34 MIPI_DSI1.4 R121.2 RGBLCD.38  [also labelled TWI0-SCL]
CT1_SDA: LVDS1.33 MIPI_DSI1.5 R123.2 RGBLCD.36  [also labelled TWI0-SDA]
CT2_INT: C59.1 MIPI_DSI2.3 R128.2  [also labelled TP2-INT]
CT2_RST: MIPI_DSI2.6 R130.2  [also labelled TP2-RST]
CT2_SCL: MIPI_DSI2.4 R120.2  [also labelled TWI1-SCL]
CT2_SDA: MIPI_DSI2.5 R122.2  [also labelled TWI1-SDA]
DSI0-CK_N: MIPI_DSI1.14 R91.2
DSI0-CK_P: MIPI_DSI1.13 R89.2
DSI0-D0_N: MIPI_DSI1.17 R83.2
DSI0-D0_P: MIPI_DSI1.16 R81.2
DSI0-D1_N: MIPI_DSI1.11 R87.2
DSI0-D1_P: MIPI_DSI1.10 R85.2
DSI0-D2_N: MIPI_DSI1.20 R95.2
DSI0-D2_P: MIPI_DSI1.19 R93.2
DSI0-D3_N: MIPI_DSI1.23 R99.2
DSI0-D3_P: MIPI_DSI1.22 R97.2
DSI1-CK_N: MIPI_DSI2.14 R111.2
DSI1-CK_P: MIPI_DSI2.13 R109.2
DSI1-D0_N: MIPI_DSI2.17 R103.2
DSI1-D0_P: MIPI_DSI2.16 R101.2
DSI1-D1_N: MIPI_DSI2.11 R107.2
DSI1-D1_P: MIPI_DSI2.10 R105.2
DSI1-D2_N: MIPI_DSI2.20 R115.2
DSI1-D2_P: MIPI_DSI2.19 R113.2
DSI1-D3_N: MIPI_DSI2.23 R119.2
DSI1-D3_P: MIPI_DSI2.22 R117.2
GPADC3: MIPI_DSI1.8
GPADC4: MIPI_DSI2.8
LCD0-CLK: R116.1 RGBLCD.30  [also labelled PD18]
LCD0-DATA0: RGBLCD.21  [also labelled PB0]
LCD0-DATA1: RGBLCD.22  [also labelled PB1]
LCD0-DATA2: R80.1 RGBLCD.23  [also labelled PD0]
LCD0-DATA3: R82.1 RGBLCD.24  [also labelled PD1]
LCD0-DATA4: R84.1 RGBLCD.25  [also labelled PD2]
LCD0-DATA5: R86.1 RGBLCD.26  [also labelled PD3]
LCD0-DATA6: R88.1 RGBLCD.27  [also labelled PD4]
LCD0-DATA7: R90.1 RGBLCD.28  [also labelled PD5]
LCD0-DATA8: RGBLCD.12  [also labelled PB2]
LCD0-DATA9: RGBLCD.13  [also labelled PB3]
LCD0-DATA10: R92.1 RGBLCD.14  [also labelled PD6]
LCD0-DATA11: R94.1 RGBLCD.15  [also labelled PD7]
LCD0-DATA12: R96.1 RGBLCD.16  [also labelled PD8]
LCD0-DATA13: R98.1 RGBLCD.17  [also labelled PD9]
LCD0-DATA14: R100.1 RGBLCD.18  [also labelled PD10]
LCD0-DATA15: R102.1 RGBLCD.19  [also labelled PD11]
LCD0-DATA16: RGBLCD.3  [also labelled PB7]
LCD0-DATA17: RGBLCD.4  [also labelled PB8]
LCD0-DATA18: R104.1 RGBLCD.5  [also labelled PD12]
LCD0-DATA19: R106.1 RGBLCD.6  [also labelled PD13]
LCD0-DATA20: R108.1 RGBLCD.7  [also labelled PD14]
LCD0-DATA21: R110.1 RGBLCD.8  [also labelled PD15]
LCD0-DATA22: R112.1 RGBLCD.9  [also labelled PD16]
LCD0-DATA23: R114.1 RGBLCD.10  [also labelled PD17]
LCD0-DE: R118.1 RGBLCD.33  [also labelled PD19]
LCD0-HSYNC: RGBLCD.31  [also labelled PD20]
LCD0-VSYNC: RGBLCD.32  [also labelled PD21]
LCD1-BL: LVDS1.27 MIPI_DSI1.7 R125.2 RGBLCD.34
LCD1-RST: R127.2 R133.2 RGBLCD.40
LCD2-BL: MIPI_DSI2.7 R124.2
LCD2-RST: R126.2 R132.2
LVDS0-CK_N: LVDS1.17 R94.2 R95.1
LVDS0-CK_P: LVDS1.18 R92.2 R93.1
LVDS0-D0_N: LVDS1.8 R82.2 R83.1
LVDS0-D0_P: LVDS1.9 R80.2 R81.1
LVDS0-D1_N: LVDS1.11 R86.2 R87.1
LVDS0-D1_P: LVDS1.12 R84.2 R85.1
LVDS0-D2_N: LVDS1.14 R90.2 R91.1
LVDS0-D2_P: LVDS1.15 R88.2 R89.1
LVDS0-D3_N: LVDS1.20 R98.2 R99.1
LVDS0-D3_P: LVDS1.21 R96.2 R97.1
LVDS1-CK_N: R114.2 R115.1
LVDS1-CK_P: R112.2 R113.1
LVDS1-D0_N: R102.2 R103.1
LVDS1-D0_P: R100.2 R101.1
LVDS1-D1_N: R106.2 R107.1
LVDS1-D1_P: R104.2 R105.1
LVDS1-D2_N: R110.2 R111.1
LVDS1-D2_P: R108.2 R109.1
LVDS1-D3_N: R118.2 R119.1
LVDS1-D3_P: R116.2 R117.1
MIPI1_RST: MIPI_DSI1.25 R133.1 R135.2
MIPI2_RST: MIPI_DSI2.25 R132.1 R134.2

Not connected (* = marked no-connect by the designer): LVDS1 1* 4* 5* 6* 23* 24* 26* 29* 31* 32* 35* 37* 38* 39* 40*; RGBLCD 37*

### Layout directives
differential pair: DSI0-CK_N, DSI0-CK_P, DSI0-D0_N, DSI0-D0_P, DSI0-D1_N, DSI0-D1_P, DSI0-D2_N, DSI0-D2_P, DSI0-D3_N, DSI0-D3_P, DSI1-CK_N, DSI1-CK_P, DSI1-D0_N, DSI1-D0_P, DSI1-D1_N, DSI1-D1_P, DSI1-D2_N, DSI1-D2_P, DSI1-D3_N, DSI1-D3_P, LVDS0-CK_N, LVDS0-CK_P, LVDS0-D0_N, LVDS0-D0_P, LVDS0-D1_N, LVDS0-D1_P, LVDS0-D2_N, LVDS0-D2_P, LVDS0-D3_N, LVDS0-D3_P, LVDS1-CK_N, LVDS1-CK_P, LVDS1-D0_N, LVDS1-D0_P, LVDS1-D1_N, LVDS1-D1_P, LVDS1-D2_N, LVDS1-D2_P, LVDS1-D3_N, LVDS1-D3_P

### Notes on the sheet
- RGBLCD
- T527芯片最多支持双屏异显，所以在设计的时候需要合理的考虑实际情况
- 开发板上的LVDS接口和MIPI接口以及RGB接口都是从一组引脚上复用出来的，所以这几个接口存在复用关系不能同时使用，开发板为了方便大家使用故直接串联了，在项目上不建议如此使用。
- RGB走线尽量等长，若是用用于LVDS或者MIPI，差分走线需要做等长处理以及走线阻抗为差分100欧
- 串接电阻是用于多接口预留阻抗匹配使用，若使用单接口请去掉这部分
- LVDS0和LVDS1只能同显或者组成8通道LVDS，所以开发板取消了LVDS1接口
- LVDS0
- LVDS1
- MIPI0
- MIPI1

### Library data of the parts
C58-C66 C67#2 C68#2 = C: 无极性电容; BOM名称: 无极性贴片电容; 版权归属: 正点原子
LVDS1 LVDS2 = FPC-40P: FPC连接器; 版权归属: 正点原子; Parameter: 接口器件
MIPI_DSI1 MIPI_DSI2 = FPC-26P: FPC连接器; 版权归属: 正点原子; Parameter: 接口器件
R80-R135 = R: 电阻; BOM名称: 贴片电阻; 版权归属: 正点原子
RGBLCD = FPC-40: FPC-40P-0.5mm

## Sheet 07_ATK_T527_HDMI&DP.SchDoc
size A4; Author: ALIENTEK; Revision: 0; Version: V1.0; SheetSize: A4
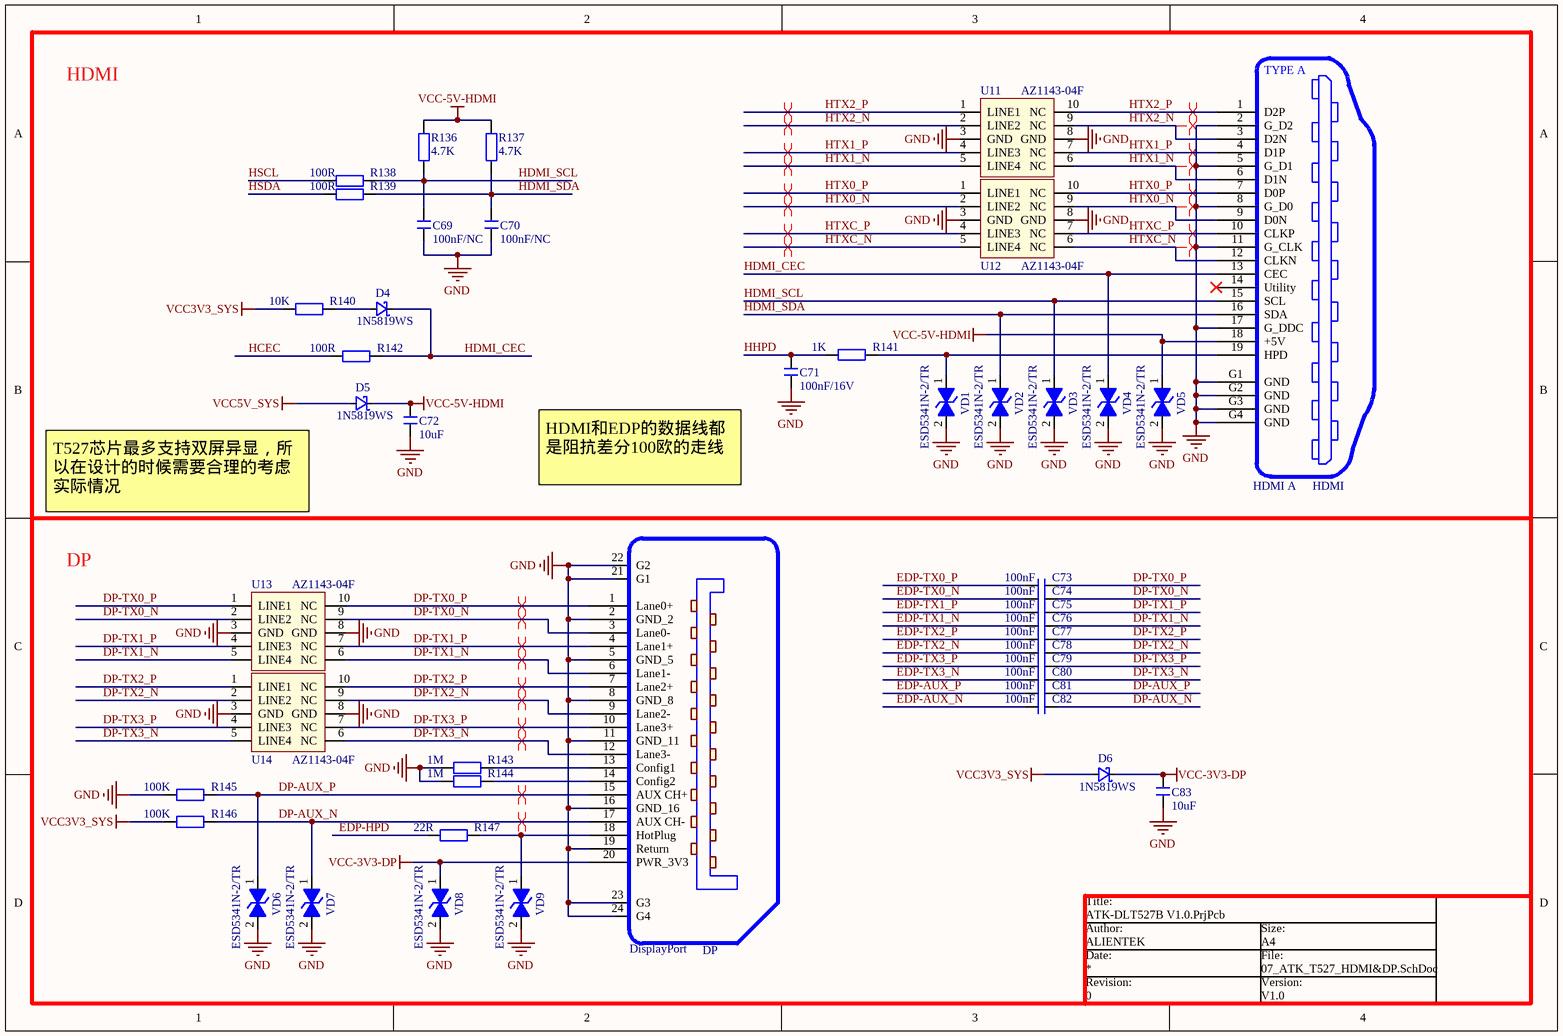
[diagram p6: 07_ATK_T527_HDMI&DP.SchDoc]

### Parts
C69  100nF/NC  [C 0402]
C70  100nF/NC  [C 0402]
C71  100nF/16V  [C 0402]
C72  10uF  [C 0603]
C73  100nF  [C 0402]
C74  100nF  [C 0402]
C75  100nF  [C 0402]
C76  100nF  [C 0402]
C77  100nF  [C 0402]
C78  100nF  [C 0402]
C79  100nF  [C 0402]
C80  100nF  [C 0402]
C81  100nF  [C 0402]
C82  100nF  [C 0402]
C83  10uF  [C 0603]
D4  1N5819WS  [SOD-323]
D5  1N5819WS  [SOD-323]
D6  1N5819WS  [SOD-323]
DP  DisplayPort  [DisplayPort-20]
HDMI  HDMI A  [HDMI-A-19P]
R136  4.7K  [R 0402]
R137  4.7K  [R 0402]
R138  100R  [R 0402]
R139  100R  [R 0402]
R140  10K  [R 0402]
R141  1K  [R 0402]
R142  100R  [R 0402]
R143  1M  [R 0402]
R144  1M  [R 0402]
R145  100K  [R 0402]
R146  100K  [R 0402]
R147  22R  [R 0402]
U11  AZ1143-04F  [DFN2510P10E]
U12  AZ1143-04F  [DFN2510P10E]
U13  AZ1143-04F  [DFN2510P10E]
U14  AZ1143-04F  [DFN2510P10E]
VD1  ESD5341N-2/TR  [ESD0402]
VD2  ESD5341N-2/TR  [ESD0402]
VD3  ESD5341N-2/TR  [ESD0402]
VD4  ESD5341N-2/TR  [ESD0402]
VD5  ESD5341N-2/TR  [ESD0402]
VD6  ESD5341N-2/TR  [ESD0402]
VD7  ESD5341N-2/TR  [ESD0402]
VD8  ESD5341N-2/TR  [ESD0402]
VD9  ESD5341N-2/TR  [ESD0402]

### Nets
GND: C69.1 C70.1 C71.1 C72.1 C83.1 DP.2(GND_2) DP.5(GND_5) DP.8(GND_8) DP.11(GND_11) DP.16(GND_16) DP.19(Return) DP.21(G1) DP.22(G2) DP.23(G3) DP.24(G4) HDMI.2(G_D2) HDMI.5(G_D1) HDMI.8(G_D0) HDMI.11(G_CLK) HDMI.17(G_DDC) HDMI.G1(GND) HDMI.G2(GND) HDMI.G3(GND) HDMI.G4(GND) R143.1 R144.1 R145.1 U11.3(GND) U11.8(GND) U12.3(GND) U12.8(GND) U13.3(GND) U13.8(GND) U14.3(GND) U14.8(GND) VD1.2 VD2.2 VD3.2 VD4.2 VD5.2 VD6.2 VD7.2 VD8.2 VD9.2
VCC3V3_SYS: D6.1(A) R140.1 R146.1
VCC5V_SYS: D5.1(A)
VCC-3V3-DP: C83.2 D6.2(K) DP.20(PWR_3V3) VD8.1
VCC-5V-HDMI: C72.2 D5.2(K) HDMI.18(+5V) R136.2 R137.2 VD5.1
DP-AUX_N: C82.2 DP.17(AUX_CH-) R146.2 VD7.1
DP-AUX_P: C81.2 DP.15(AUX_CH+) R145.2 VD6.1
DP-TX0_N: C74.2 DP.3(Lane0-) U13.2(LINE2) U13.9(NC)
DP-TX0_P: C73.2 DP.1(Lane0+) U13.1(LINE1) U13.10(NC)
DP-TX1_N: C76.2 DP.6(Lane1-) U13.5(LINE4) U13.6(NC)
DP-TX1_P: C75.2 DP.4(Lane1+) U13.4(LINE3) U13.7(NC)
DP-TX2_N: C78.2 DP.9(Lane2-) U14.2(LINE2) U14.9(NC)
DP-TX2_P: C77.2 DP.7(Lane2+) U14.1(LINE1) U14.10(NC)
DP-TX3_N: C80.2 DP.12(Lane3-) U14.5(LINE4) U14.6(NC)
DP-TX3_P: C79.2 DP.10(Lane3+) U14.4(LINE3) U14.7(NC)
EDP-AUX_N: C82.1
EDP-AUX_P: C81.1
EDP-HPD: R147.1
EDP-TX0_N: C74.1
EDP-TX0_P: C73.1
EDP-TX1_N: C76.1
EDP-TX1_P: C75.1
EDP-TX2_N: C78.1
EDP-TX2_P: C77.1
EDP-TX3_N: C80.1
EDP-TX3_P: C79.1
HCEC: R142.1
HDMI_CEC: D4.2(K) HDMI.13(CEC) R142.2 VD4.1
HDMI_SCL: C69.2 HDMI.15(SCL) R136.1 R138.2 VD3.1
HDMI_SDA: C70.2 HDMI.16(SDA) R137.1 R139.2 VD2.1
HHPD: C71.2 R141.1
HSCL: R138.1
HSDA: R139.1
HTX0_N: HDMI.9(D0N) U12.2(LINE2) U12.9(NC)
HTX0_P: HDMI.7(D0P) U12.1(LINE1) U12.10(NC)
HTX1_N: HDMI.6(D1N) U11.5(LINE4) U11.6(NC)
HTX1_P: HDMI.4(D1P) U11.4(LINE3) U11.7(NC)
HTX2_N: HDMI.3(D2N) U11.2(LINE2) U11.9(NC)
HTX2_P: HDMI.1(D2P) U11.1(LINE1) U11.10(NC)
HTXC_N: HDMI.12(CLKN) U12.5(LINE4) U12.6(NC)
HTXC_P: HDMI.10(CLKP) U12.4(LINE3) U12.7(NC)
NetD4_1: D4.1(A) R140.2
NetDP_13: DP.13(Config1) R143.2
NetDP_14: DP.14(Config2) R144.2
NetDP_18: DP.18(HotPlug) R147.2 VD9.1
NetHDMI_19: HDMI.19(HPD) R141.2 VD1.1

Not connected (* = marked no-connect by the designer): HDMI 14(Utility)*

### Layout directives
differential pair: DP-AUX_N, DP-AUX_P, DP-TX0_N, DP-TX0_P, DP-TX1_N, DP-TX1_P, DP-TX2_N, DP-TX2_P, DP-TX3_N, DP-TX3_P, HTX0_N, HTX0_P, HTX1_N, HTX1_P, HTX2_N, HTX2_P, HTXC_N, HTXC_P

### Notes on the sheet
- HDMI
- T527芯片最多支持双屏异显，所以在设计的时候需要合理的考虑实际情况
- HDMI和EDP的数据线都是阻抗差分100欧的走线
- DP

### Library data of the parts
C69-C83 = C: 无极性电容; BOM名称: 无极性贴片电容; 版权归属: 正点原子
D4-D6 = 1N5819HW-7-F: 肖特基二极管 40V  450mV@1A; 版权归属: 正点原子
DP = DisplayPort: 全尺寸DP接口
HDMI = HDMI-A-19P
R136-R147 = R: 电阻; BOM名称: 贴片电阻; 版权归属: 正点原子
U11-U14 = AZ1143-04F: ESD保护二极管阵列
VD1-VD9 = ESD5341N: ESD二极管-单向

## Sheet 08_ATK_T527_USBOTG&HOST.SchDoc
size A3; Date: 13; Author: ALIENTEK; Version: V1.0; SheetSize: A3
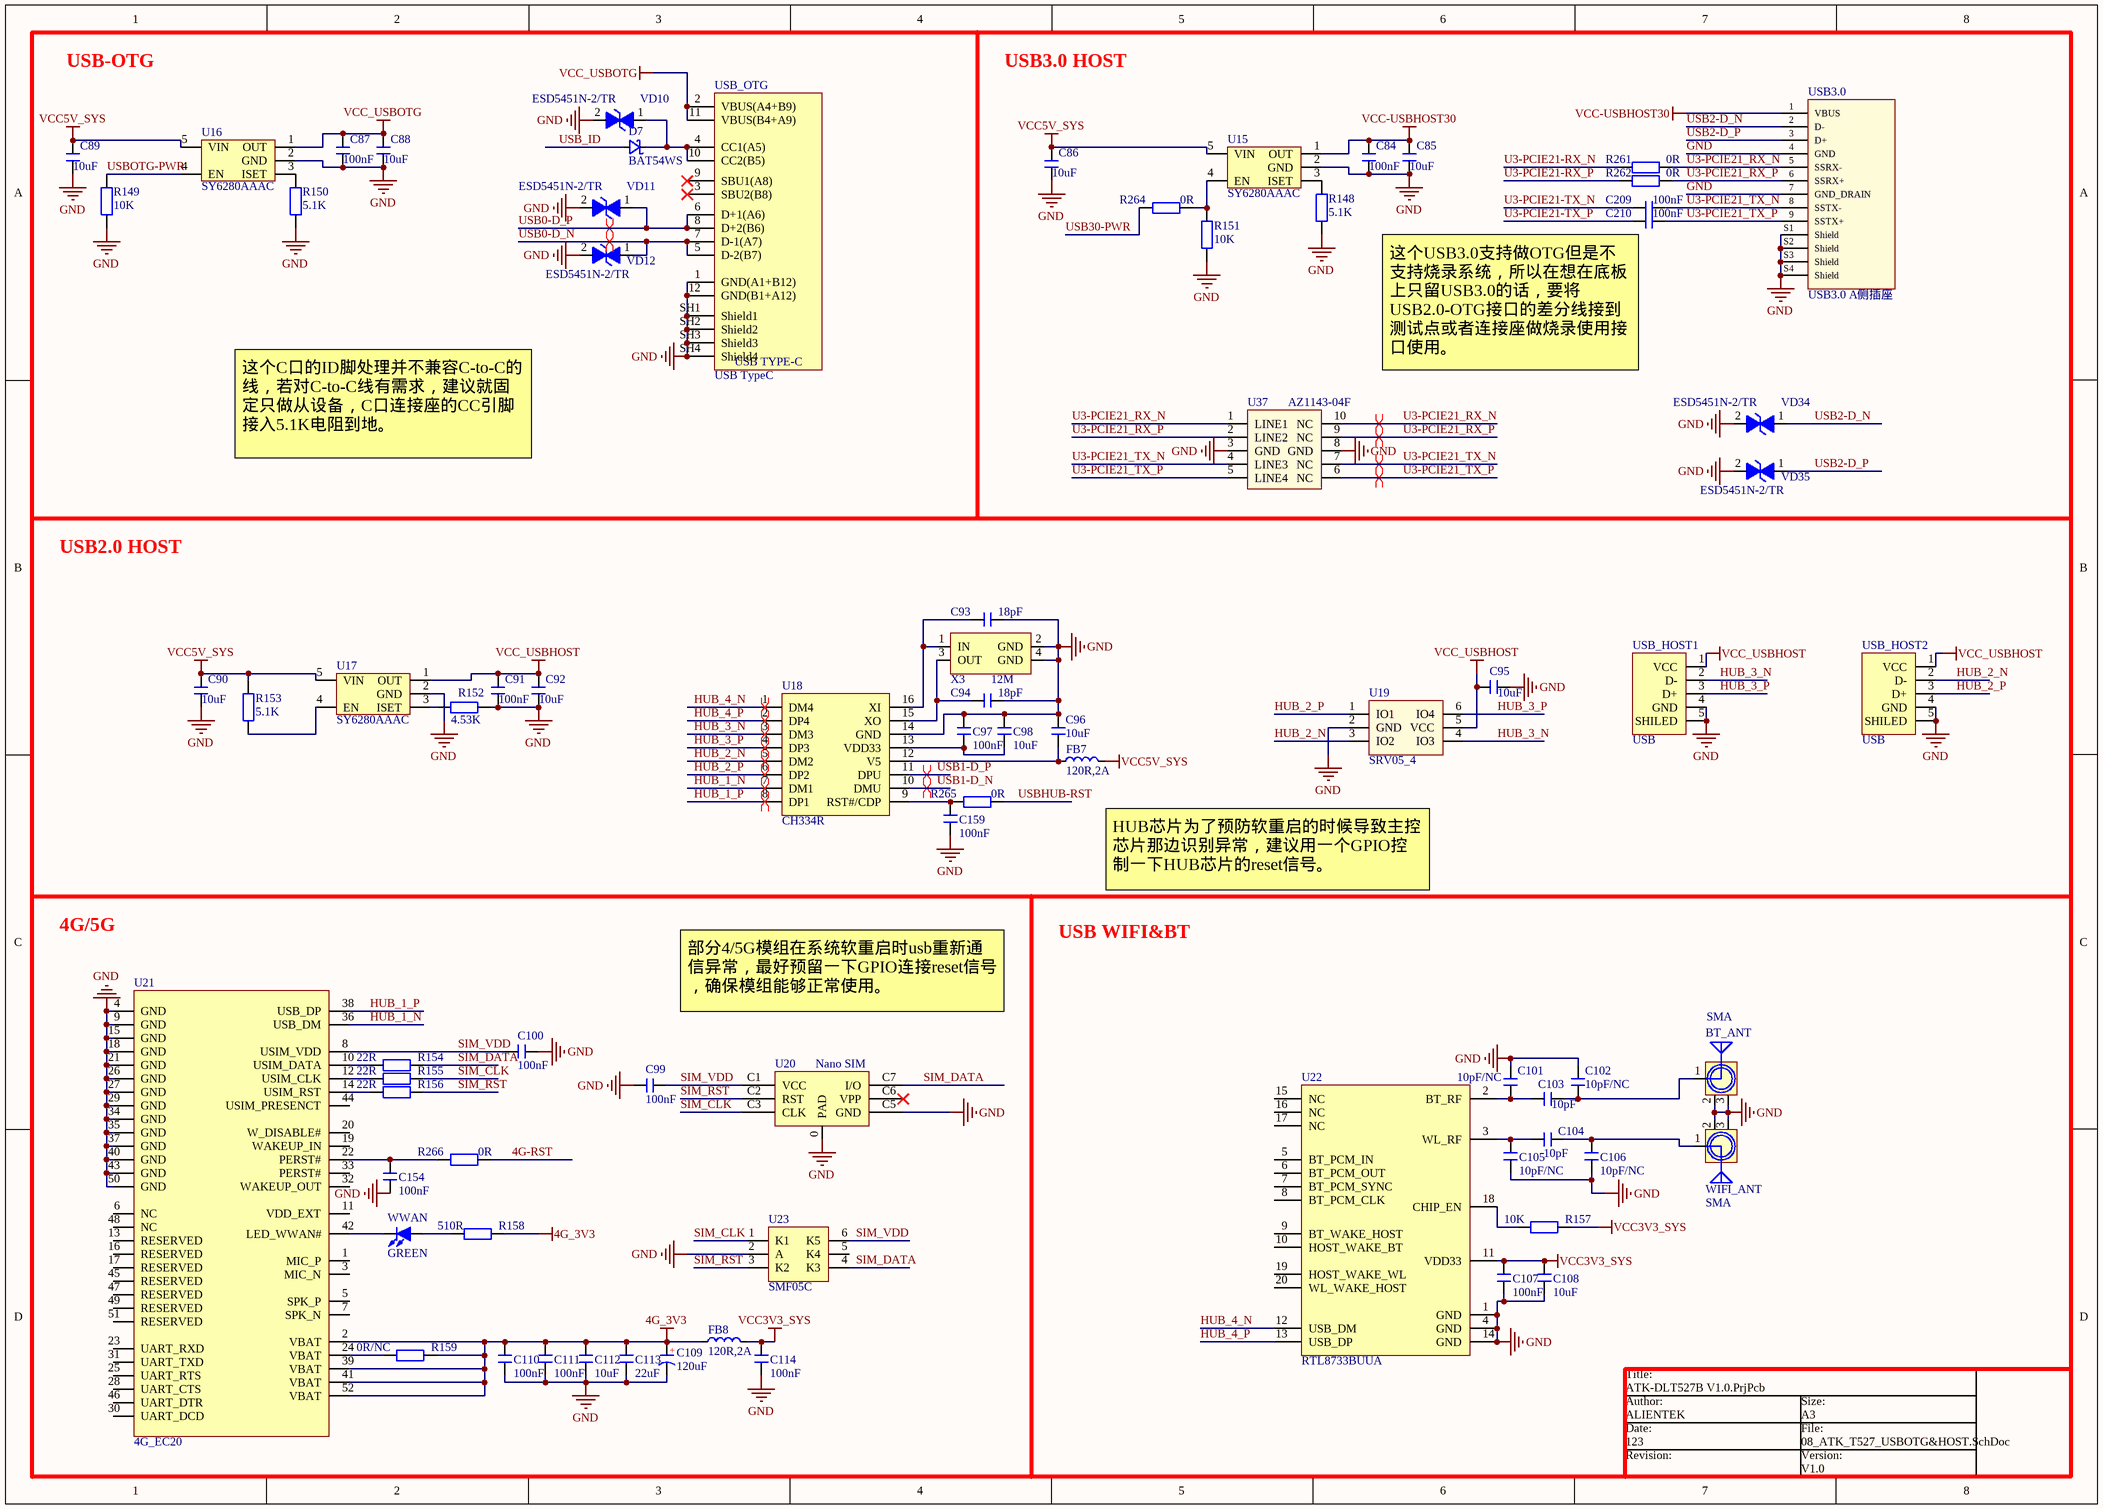
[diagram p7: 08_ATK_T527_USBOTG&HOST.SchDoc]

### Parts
BT_ANT  SMA  [SMA-KWE]
C84  100nF  [C 0402]
C85  10uF  [C 0603]
C86  10uF  [C 0603]
C87  100nF  [C 0402]
C88  10uF  [C 0603]
C89  10uF  [C 0603]
C90  10uF  [C 0603]
C91  100nF  [C 0402]
C92  10uF  [C 0603]
C93  18pF  [C 0402]
C94  18pF  [C 0402]
C95  10uF  [C 0603]
C96  10uF  [C 0603]
C97  100nF  [C 0402]
C98  10uF  [C 0603]
C99  100nF  [C 0402]
C100  100nF  [C 0402]
C101  10pF/NC  [C 0402]
C102  10pF/NC  [C 0402]
C103  10pF  [C 0402]
C104  10pF  [C 0402]
C105  10pF/NC  [C 0402]
C106  10pF/NC  [C 0402]
C107  100nF  [C 0402]
C108  10uF  [C 0603]
C109  120uF  [CM D(6.3*7.7)]
C110  100nF  [C 0402]
C111  100nF  [C 0402]
C112  10uF  [C 0603]
C113  22uF  [C 0603]
C114  100nF  [C 0402]
C154  100nF  [C 0402]
C159  100nF  [C 0402]
C209  100nF  [C 0402]
C210  100nF  [C 0402]
D7  BAT54WS  [SOD-323]
FB7  120R,2A  [L 0603]
FB8  120R,2A  [L 0603]
R148  5.1K  [R 0402]
R149  10K  [R 0402]
R150  5.1K  [R 0402]
R151  10K  [R 0402]
R152  4.53K  [R 0402]
R153  5.1K  [R 0402]
R154  22R  [R 0402]
R155  22R  [R 0402]
R156  22R  [R 0402]
R157  10K  [R 0402]
R158  510R  [R 0402]
R159  0R/NC  [R 0402]
R261  0R  [R 0402]
R262  0R  [R 0402]
R264  0R  [R 0402]
R265  0R  [R 0402]
R266  0R  [R 0402]
U15  SY6280AAAC  [SOT23-5N]
U16  SY6280AAAC  [SOT23-5N]
U17  SY6280AAAC  [SOT23-5N]
U18  CH334R  [QSOP16]
U19  SRV05_4  [SOT23-6L]
U20  Nano SIM  [Nano SIM 7P]
U21  4G_EC20  [Mini PCIE 52P]
U22  RTL8733BUUA  [RTL8733BUBUA]
U23  SMF05C  [SOT363-6L]
U37  AZ1143-04F  [DFN2510P10E]
USB3.0  USB3.0 A侧插座  [USB3.0 A侧插]
USB_HOST1  USB  [USB-A/S_E]
USB_HOST2  USB  [USB-A/S_E]
USB_OTG  USB TypeC  [USB2.0 Type-C]
VD10  ESD5451N-2/TR  [ESD0402]
VD11  ESD5451N-2/TR  [ESD0402]
VD12  ESD5451N-2/TR  [ESD0402]
VD34  ESD5451N-2/TR  [ESD0402]
VD35  ESD5451N-2/TR  [ESD0402]
WIFI_ANT  SMA  [SMA-KWE]
WWAN  GREEN  [LED 0805G]
X3  12M  [XTAL-3225]

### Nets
4G_3V3: C109.1(A) C110.2 C111.2 C112.2 C113.2 FB8.1 R158.2 R159.2 U21.2(VBAT) U21.39(VBAT) U21.41(VBAT) U21.52(VBAT)
GND: BT_ANT.2(GND) BT_ANT.3(GND) C84.2 C85.2 C86.2 C87.2 C88.2 C89.2 C90.2 C91.2 C92.2 C93.2 C94.2 C95.2 C96.1 C97.1 C98.1 C99.2 C100.2 C101.2 C102.2 C105.1 C106.1 C107.1 C108.1 C109.2(K) C110.1 C111.1 C112.1 C113.1 C114.1 C154.1 C159.1 R148.2 R149.2 R150.2 R151.2 R152.1 U15.2(GND) U16.2(GND) U17.2(GND) U18.14(GND) U19.2(GND) U20.0(PAD) U20.C5(GND) U21.4(GND) U21.9(GND) U21.15(GND) U21.18(GND) U21.21(GND) U21.26(GND) U21.27(GND) U21.29(GND) U21.34(GND) U21.35(GND) U21.37(GND) U21.40(GND) U21.43(GND) U21.50(GND) U22.1(GND) U22.4(GND) U22.14(GND) U23.2(A) U37.3(GND) U37.8(GND) USB3.0.4(GND) USB3.0.7(GND_DRAIN) USB3.0.S1(Shield) USB3.0.S2(Shield) USB3.0.S3(Shield) USB3.0.S4(Shield) USB_HOST1.4(GND) USB_HOST1.5(SHILED) USB_HOST2.4(GND) USB_HOST2.5(SHILED) USB_OTG.1(GND(A1+B12)) USB_OTG.12(GND(B1+A12)) USB_OTG.SH1(Shield1) USB_OTG.SH2(Shield2) USB_OTG.SH3(Shield3) USB_OTG.SH4(Shield4) VD10.2 VD11.2 VD12.2 VD34.2 VD35.2 WIFI_ANT.2(GND) WIFI_ANT.3(GND) X3.2(GND) X3.4(GND)
VCC3V3_SYS: C107.2 C108.2 C114.2 FB8.2 R157.2 U22.11(VDD33)
VCC5V_SYS: C86.1 C89.1 C90.1 FB7.2 R153.1 U15.5(VIN) U16.5(VIN) U17.5(VIN)
VCC-USBHOST30: C84.1 C85.1 U15.1(OUT) USB3.0.1(VBUS)
VCC_USBHOST: C91.1 C92.1 C95.1 U17.1(OUT) U19.5(VCC) USB_HOST1.1(VCC) USB_HOST2.1(VCC)
VCC_USBOTG: C87.1 C88.1 U16.1(OUT) USB_OTG.2(VBUS(A4+B9)) USB_OTG.11(VBUS(B4+A9))
4G-RST: R266.2
HUB_1_N: U18.7(DM1) U21.36(USB_DM)
HUB_1_P: U18.8(DP1) U21.38(USB_DP)
HUB_2_N: U18.5(DM2) U19.3(IO2) USB_HOST2.2(D-)
HUB_2_P: U18.6(DP2) U19.1(IO1) USB_HOST2.3(D+)
HUB_3_N: U18.3(DM3) U19.4(IO3) USB_HOST1.2(D-)
HUB_3_P: U18.4(DP3) U19.6(IO4) USB_HOST1.3(D+)
HUB_4_N: U18.1(DM4) U22.12(USB_DM)
HUB_4_P: U18.2(DP4) U22.13(USB_DP)
SIM_CLK: R155.2 U20.C3(CLK) U23.1(K1)
SIM_DATA: R154.2 U20.C7(I/O) U23.4(K3)
SIM_RST: R156.2 U20.C2(RST) U23.3(K2)
SIM_VDD: C99.1 C100.1 U20.C1(VCC) U21.8(USIM_VDD) U23.6(K5)
U3-PCIE21-RX_N: R261.1
U3-PCIE21-RX_P: R262.1
U3-PCIE21-TX_N: C209.1
U3-PCIE21-TX_P: C210.1
U3-PCIE21_RX_N: R261.2 U37.1(LINE1) U37.10(NC) USB3.0.5(SSRX-)
U3-PCIE21_RX_P: R262.2 U37.2(LINE2) U37.9(NC) USB3.0.6(SSRX+)
U3-PCIE21_TX_N: C209.2 U37.4(LINE3) U37.7(NC) USB3.0.8(SSTX-)
U3-PCIE21_TX_P: C210.2 U37.5(LINE4) U37.6(NC) USB3.0.9(SSTX+)
USB0-D_N: USB_OTG.5(D-2(B7)) USB_OTG.7(D-1(A7)) VD12.1
USB0-D_P: USB_OTG.6(D+1(A6)) USB_OTG.8(D+2(B6)) VD11.1
USB1-D_N: U18.10(DMU)
USB1-D_P: U18.11(DPU)
USB2-D_N: USB3.0.2(D-) VD34.1
USB2-D_P: USB3.0.3(D+) VD35.1
USB30-PWR: R264.1  [project net PH19]
USB_ID: D7.1(A)  [project net PH11]
USBHUB-RST: R265.2  [project net LVDS3-D3_P]
USBOTG-PWR: R149.1 U16.4(EN)  [project net PH12]
NetBT_ANT_1: BT_ANT.1(ANT) C102.1 C103.1
NetC93_1: C93.1 U18.16(XI) X3.1(IN)
NetC94_1: C94.1 U18.15(XO) X3.3(OUT)
NetC96_2: C96.2 FB7.1 U18.12(V5)
NetC97_2: C97.2 C98.2 U18.13(VDD33)
NetC101_1: C101.1 C103.2 U22.2(BT_RF)
NetC104_1: C104.1 C106.2 WIFI_ANT.1(ANT)
NetC104_2: C104.2 C105.2 U22.3(WL_RF)
NetC154_2: C154.2 R266.1 U21.22(PERST#)
NetC159_2: C159.2 R265.1 U18.9(RST#/CDP)
NetD7_2: D7.2(K) USB_OTG.4(CC1(A5)) USB_OTG.10(CC2(B5)) VD10.1
NetR148_1: R148.1 U15.3(ISET)
NetR150_1: R150.1 U16.3(ISET)
NetR151_1: R151.1 R264.2 U15.4(EN)
NetR152_2: R152.2 U17.3(ISET)
NetR153_2: R153.2 U17.4(EN)
NetR154_1: R154.1 U21.10(USIM_DATA)
NetR155_1: R155.1 U21.12(USIM_CLK)
NetR156_1: R156.1 U21.14(USIM_RST)
NetR157_1: R157.1 U22.18(CHIP_EN)
NetR158_1: R158.1 WWAN.1(A)
NetR159_1: R159.1 U21.24(VBAT)
NetU21_42: U21.42(LED_WWAN#) WWAN.2(K)

Not connected (* = marked no-connect by the designer): U20 C4(NC) C6(VPP)*; U21 1(MIC_P) 3(MIC_N) 5(SPK_P) 6(NC) 7(SPK_N) 11(VDD_EXT) 13(RESERVED) 16(RESERVED) 17(RESERVED) 19(WAKEUP_IN) 20(W_DISABLE#) 23(UART_RXD) 25(UART_RTS) 28(UART_CTS) 30(UART_DCD) 31(UART_TXD) 32(WAKEUP_OUT) 33(PERST#) 44(USIM_PRESENCT) 45(RESERVED) 46(UART_DTR) 47(RESERVED) 48(NC) 49(RESERVED) 51(RESERVED); U22 5(BT_PCM_IN) 6(BT_PCM_OUT) 7(BT_PCM_SYNC) 8(BT_PCM_CLK) 9(BT_WAKE_HOST) 10(HOST_WAKE_BT) 15(NC) 16(NC) 17(NC) 19(HOST_WAKE_WL) 20(WL_WAKE_HOST); U23 5(K4); USB_OTG 3(SBU2(B8))* 9(SBU1(A8))*

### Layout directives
differential pair: HUB_1_N, HUB_1_P, HUB_2_N, HUB_2_P, HUB_3_N, HUB_3_P, HUB_4_N, HUB_4_P, U3-PCIE21_RX_N, U3-PCIE21_RX_P, U3-PCIE21_TX_N, U3-PCIE21_TX_P, USB0-D_N, USB0-D_P, USB1-D_N, USB1-D_P

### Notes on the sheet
- USB-OTG
- USB3.0 HOST
- (near C210) 这个USB3.0支持做OTG但是不支持烧录系统，所以在想在底板上只留USB3.0的话，要将USB2.0-OTG接口的差分线接到测试点或者连接座做烧录使用接口使用。
- 这个C口的ID脚处理并不兼容C-to-C的线，若对C-to-C线有需求，建议就固定只做从设备，C口连接座的CC引脚接入5.1K电阻到地。
- USB2.0 HOST
- HUB芯片为了预防软重启的时候导致主控芯片那边识别异常，建议用一个GPIO控制一下HUB芯片的reset信号。
- 4G/5G
- USB WIFI&BT
- 部分4/5G模组在系统软重启时usb重新通信异常，最好预留一下GPIO连接reset信号，确保模组能够正常使用。

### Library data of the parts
BT_ANT WIFI_ANT = SMA: SMA-2.4G射频天线接口; 版权归属: 正点原子
C84-C108 C110-C114 C154 C159 C209 C210 = C: 无极性电容; BOM名称: 无极性贴片电容; 版权归属: 正点原子
C109 = C-CAP: 有极性电容; 版权归属: 正点原子
D7 = D: 肖特基二极管 40V  xA; 版权归属: 正点原子; BOM名称: 二极管(肖特基)
FB7 FB8 = FB: as FB1 on sheet 04_ATK_T527_NET1
R148-R159 R261 R262 R264-R266 = R: 电阻; BOM名称: 贴片电阻; 版权归属: 正点原子
U15-U17 = MT9700HT5: 功率开关(5.5V-2A); BOM名称: 稳压芯片; 版权归属: 正点原子; Parameter: 芯片
U18 = CH334R: 4端口USB HUB控制器, USB2.0
U19 = SRV05_4: ESD保护二极管阵列; Parameter: 芯片
U21 = 4G-EC20
U37 = AZ1143-04F: ESD保护二极管阵列
USB3.0 = USB3.0 A侧插
USB_HOST1 USB_HOST2 = USB-A/S: USB-A型母接口; 版权归属: 正点原子
USB_OTG = USB 2.0 Type C: 12P TypeC 母座; 版权归属: 正点原子; Parameter: 接口器件
VD10-VD12 VD34 VD35 = ESD5341N: ESD二极管-单向
WWAN = LED: BOM名称: 插件LED; 版权归属: 正点原子; Parameter: 发光二极管
X3 = XTAL-4P: as X1 on sheet 04_ATK_T527_NET1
